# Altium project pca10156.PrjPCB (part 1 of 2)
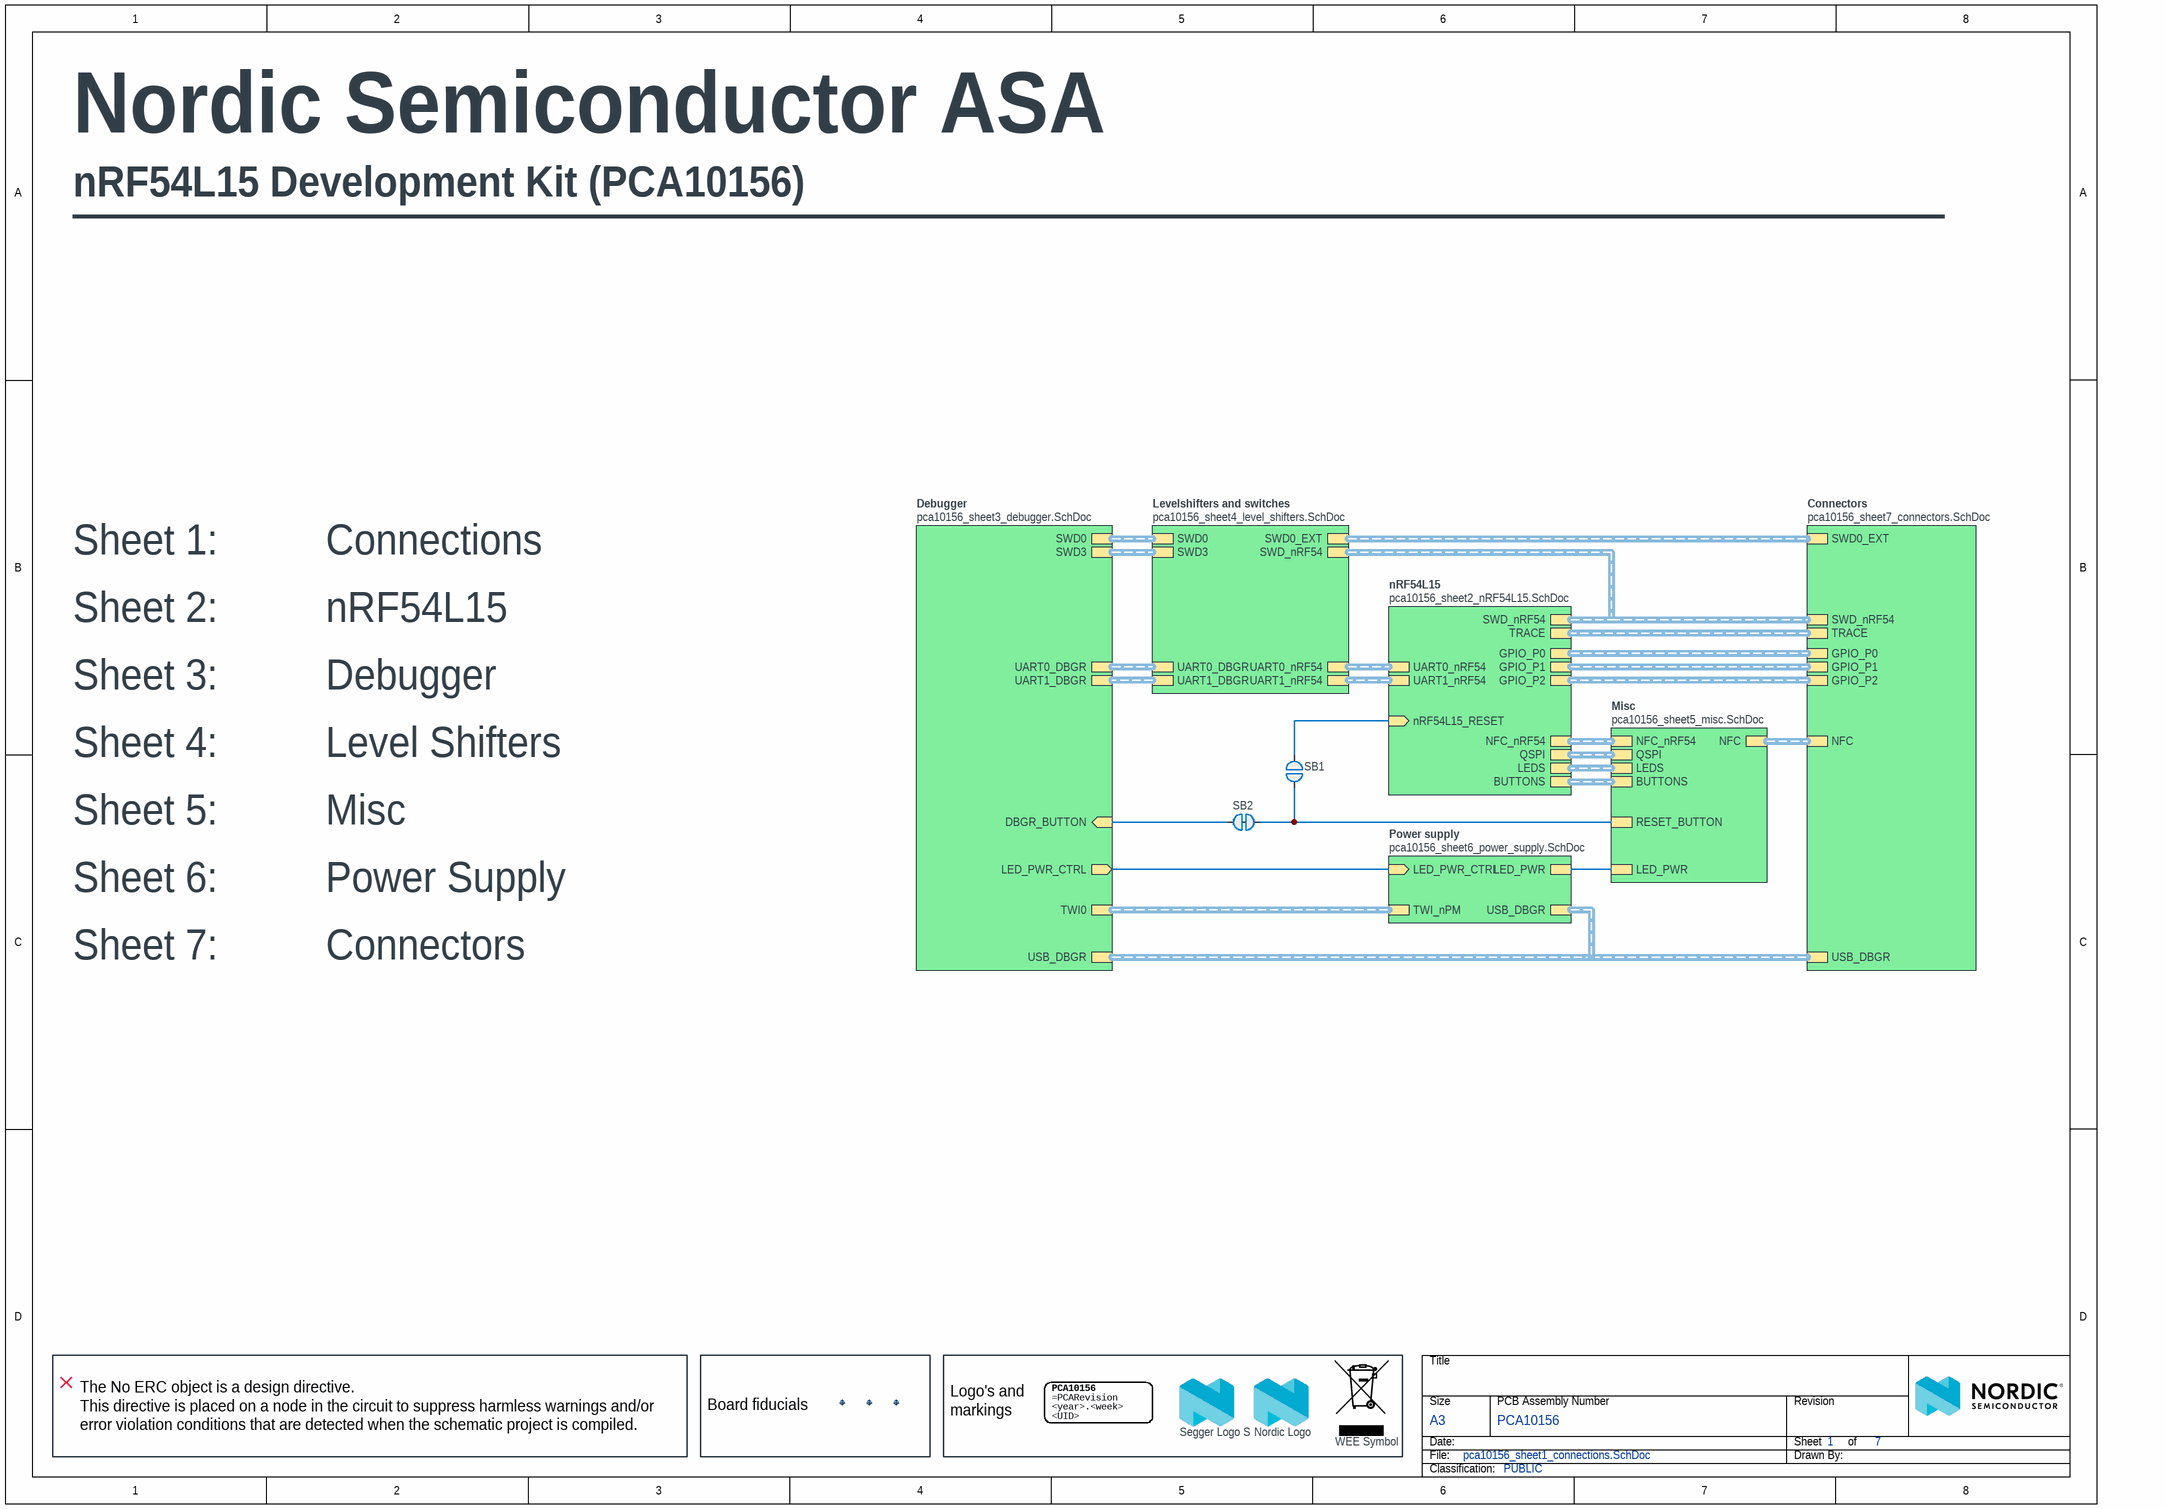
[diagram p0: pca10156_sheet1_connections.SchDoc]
BoardThickness: 1.6mm; BoardTitle: nRF54L15-DK; Classification: PUBLIC; Compliance: RoHS, REACH, Halogen-Free; Designer: STL1; Dielectric: FR-4; NrOfLayers: 4; Organization: Nordic Semiconductor; PCAName: PCA10156; PCARevision: 0.9.3; PCBNumber: 400708; PCBRevision: 0032STL1; PCBStackup: 4001; ProductName: nRF54L15-DK; SilkscreenColor: White; SoldermaskColor: Blue; SurfaceFinish: ENIG Gold
7 sheets, 207 parts. Net scope: hierarchical (ports join the sheet entries above them; power ports are global).
Board files: 400708.PcbDoc, 400708 _panel.PcbDoc
Sheets:
  pca10156_sheet1_connections.SchDoc
    nRF54L15 = pca10156_sheet2_nRF54L15.SchDoc
    Debugger = pca10156_sheet3_debugger.SchDoc
    Levelshifters and switches = pca10156_sheet4_level_shifters.SchDoc
    Misc = pca10156_sheet5_misc.SchDoc
    Power supply = pca10156_sheet6_power_supply.SchDoc
    Connectors = pca10156_sheet7_connectors.SchDoc

## Sheet pca10156_sheet1_connections.SchDoc: =BoardTitle+' - Connections'
size A3; Organization: Nordic Semiconductor; DocumentNumber: 1; Revision: 0.9.3; SheetNumber: 1; SheetTotal: 7; Author: STL1; CompanyName: Nordic Semiconductor; DrawnBy: STL1; DocumentSize: A4

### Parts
Fid1  Fiducial mark  [Fiducial]  (value not drawn)
Fid2  Fiducial mark  [Fiducial]  (value not drawn)
Fid3  Fiducial mark  [Fiducial]  (value not drawn)
LABEL1  12x12mm  [LabelSilk_12x12]  (value not drawn)
LOGO1  Nordic Logo  [NORDIC_LOGO_LYING]  (no BOM)
LOGO2  WEE Symbol  [WEE_3x4.5mm]  (no BOM)
LOGO3  Segger Logo S  [SEGGER_LOGO_S]  (no BOM)
SB1  Solderbridge  [Solderbridge]  (value not drawn)  (no BOM)
SB2  Solderbridge  [Solderbridge_Shorted]  (value not drawn)  (net tie, no BOM)

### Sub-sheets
Connectors = pca10156_sheet7_connectors.SchDoc: SWD_nRF54 (harness SWD), TRACE (harness TRACE), NFC (harness NFC), SWD0_EXT (harness SWD), GPIO_P0 (harness GPIO_P0), GPIO_P1 (harness GPIO_P1), GPIO_P2 (harness GPIO_P2), USB_DBGR (harness USB)
Debugger = pca10156_sheet3_debugger.SchDoc: DBGR_BUTTON (in), SWD0 (harness SWD), UART0_DBGR (harness UART_IMCU), USB_DBGR (harness USB), UART1_DBGR (harness UART_IMCU), TWI0 (harness TWI), SWD3 (harness SWD), LED_PWR_CTRL (out)
Levelshifters and switches = pca10156_sheet4_level_shifters.SchDoc: SWD0 (harness SWD), SWD0_EXT (harness SWD), UART0_nRF54 (harness UART), UART1_nRF54 (harness UART), SWD3 (harness SWD), SWD_nRF54 (harness SWD), UART0_DBGR (harness UART_IMCU), UART1_DBGR (harness UART_IMCU)
Misc = pca10156_sheet5_misc.SchDoc: NFC_nRF54 (harness NFC), NFC (harness NFC), BUTTONS (harness UI), LEDS (harness UI), RESET_BUTTON, QSPI (harness QSPI), LED_PWR
nRF54L15 = pca10156_sheet2_nRF54L15.SchDoc: BUTTONS (harness UI), LEDS (harness UI), TRACE (harness TRACE), NFC_nRF54 (harness NFC), GPIO_P0 (harness GPIO_P0), UART0_nRF54 (harness UART), GPIO_P1 (harness GPIO_P1), GPIO_P2 (harness GPIO_P2), UART1_nRF54 (harness UART), SWD_nRF54 (harness SWD), QSPI (harness QSPI), nRF54L15_RESET (in)
Power supply = pca10156_sheet6_power_supply.SchDoc: TWI_nPM (harness TWI), LED_PWR_CTRL (in), LED_PWR, USB_DBGR (harness USB)

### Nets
DBGR_BUTTON: SB2.2 ; sheet Debugger/DBGR_BUTTON
LED_PWR_CTRL: sheet Debugger/LED_PWR_CTRL, sheet Power supply/LED_PWR_CTRL
nRF54L15_RESET: SB1.1 ; sheet nRF54L15/nRF54L15_RESET
NetR1_2: sheet Misc/LED_PWR, sheet Power supply/LED_PWR
NetSB1_2: SB1.2 SB2.1 ; sheet Misc/RESET_BUTTON

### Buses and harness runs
harness sheet Connectors/GPIO_P0 = sheet nRF54L15/GPIO_P0
harness sheet Connectors/GPIO_P1 = sheet nRF54L15/GPIO_P1
harness sheet Connectors/GPIO_P2 = sheet nRF54L15/GPIO_P2
harness sheet Connectors/NFC = sheet Misc/NFC
harness sheet Connectors/SWD0_EXT = sheet Levelshifters and switches/SWD0_EXT
harness sheet Connectors/SWD_nRF54 = sheet Levelshifters and switches/SWD_nRF54 = sheet nRF54L15/SWD_nRF54
harness sheet Connectors/TRACE = sheet nRF54L15/TRACE
harness sheet Connectors/USB_DBGR = sheet Debugger/USB_DBGR = sheet Power supply/USB_DBGR
harness sheet Debugger/SWD0 = sheet Levelshifters and switches/SWD0
harness sheet Debugger/SWD3 = sheet Levelshifters and switches/SWD3
harness sheet Debugger/TWI0 = sheet Power supply/TWI_nPM
harness sheet Debugger/UART0_DBGR = sheet Levelshifters and switches/UART0_DBGR
harness sheet Debugger/UART1_DBGR = sheet Levelshifters and switches/UART1_DBGR
harness sheet Levelshifters and switches/UART0_nRF54 = sheet nRF54L15/UART0_nRF54
harness sheet Levelshifters and switches/UART1_nRF54 = sheet nRF54L15/UART1_nRF54
harness sheet Misc/BUTTONS = sheet nRF54L15/BUTTONS
harness sheet Misc/LEDS = sheet nRF54L15/LEDS
harness sheet Misc/NFC_nRF54 = sheet nRF54L15/NFC_nRF54
harness sheet Misc/QSPI = sheet nRF54L15/QSPI

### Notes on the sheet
- Nordic Semiconductor ASA
- nRF54L15 Development Kit (PCA10156)
- ________________________________________________________________
- Sheet 1:          Connections
- Sheet 2:          nRF54L15
- Sheet 3:          Debugger
- Sheet 4:          Level Shifters
- Sheet 5:          Misc
- Sheet 6:          Power Supply
- Sheet 7:          Connectors
- The No ERC object is a design directive.
  This directive is placed on a node in the circuit to suppress harmless warnings and/or error violation conditions that are detected when the schematic project is compiled.
- (near Fid1) Board fiducials
- (near LABEL1) Logo's and markings

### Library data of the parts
Fid1-Fid3 = Fid-Mark: Manufacturer: N.A.; Part number NEMS: 100500073; Value: N.A.; Pad Count: 1; Component Status: Active; System: Connector
LABEL1 = Label_12x12: PCA version label, stick-on, 12x12mm; Manufacturer: Ellco Etikett; Manufacturer Part Number: A33512‐01; Part number NEMS: 101200028; Component Status: Active; Pad Count: 0; Note: N.A.
LOGO1 = Nordic Logo lying: Manufacturer: N.A.; Part number NEMS: 101100001; Component Status: Active; Pad Count: 0
LOGO2 = WEEE Symbol 3x4.5mm: WEEE Directive symbol; Manufacturer: N.A.; Part number NEMS: 101100006; Component Status: Active; Pad Count: 0
LOGO3 = Segger Logo S: Segger logo, small size; Manufacturer: N.A.; Part number NEMS: 101100004; Component Status: Active; Pad Count: 0
SB1 = Solderbridge: Manufacturer: N.A.; Part number NEMS: 100500458; Pad Count: 2; Component Status: Active; System: Connector
SB2 = Solderbridge Shorted: Shorted Solderbridge; Manufacturer: N.A.; Part number NEMS: 100500459; Pad Count: 2; Component Status: Active; System: Connector

## Sheet pca10156_sheet2_nRF54L15.SchDoc: =BoardTitle+' - nRF54L15'
size A3; Organization: Nordic Semiconductor; DocumentNumber: 2; Revision: 0.9.3; SheetNumber: 2; SheetTotal: 7; Author: STL1; CompanyName: Nordic Semiconductor; DrawnBy: STL1; DocumentSize: A4
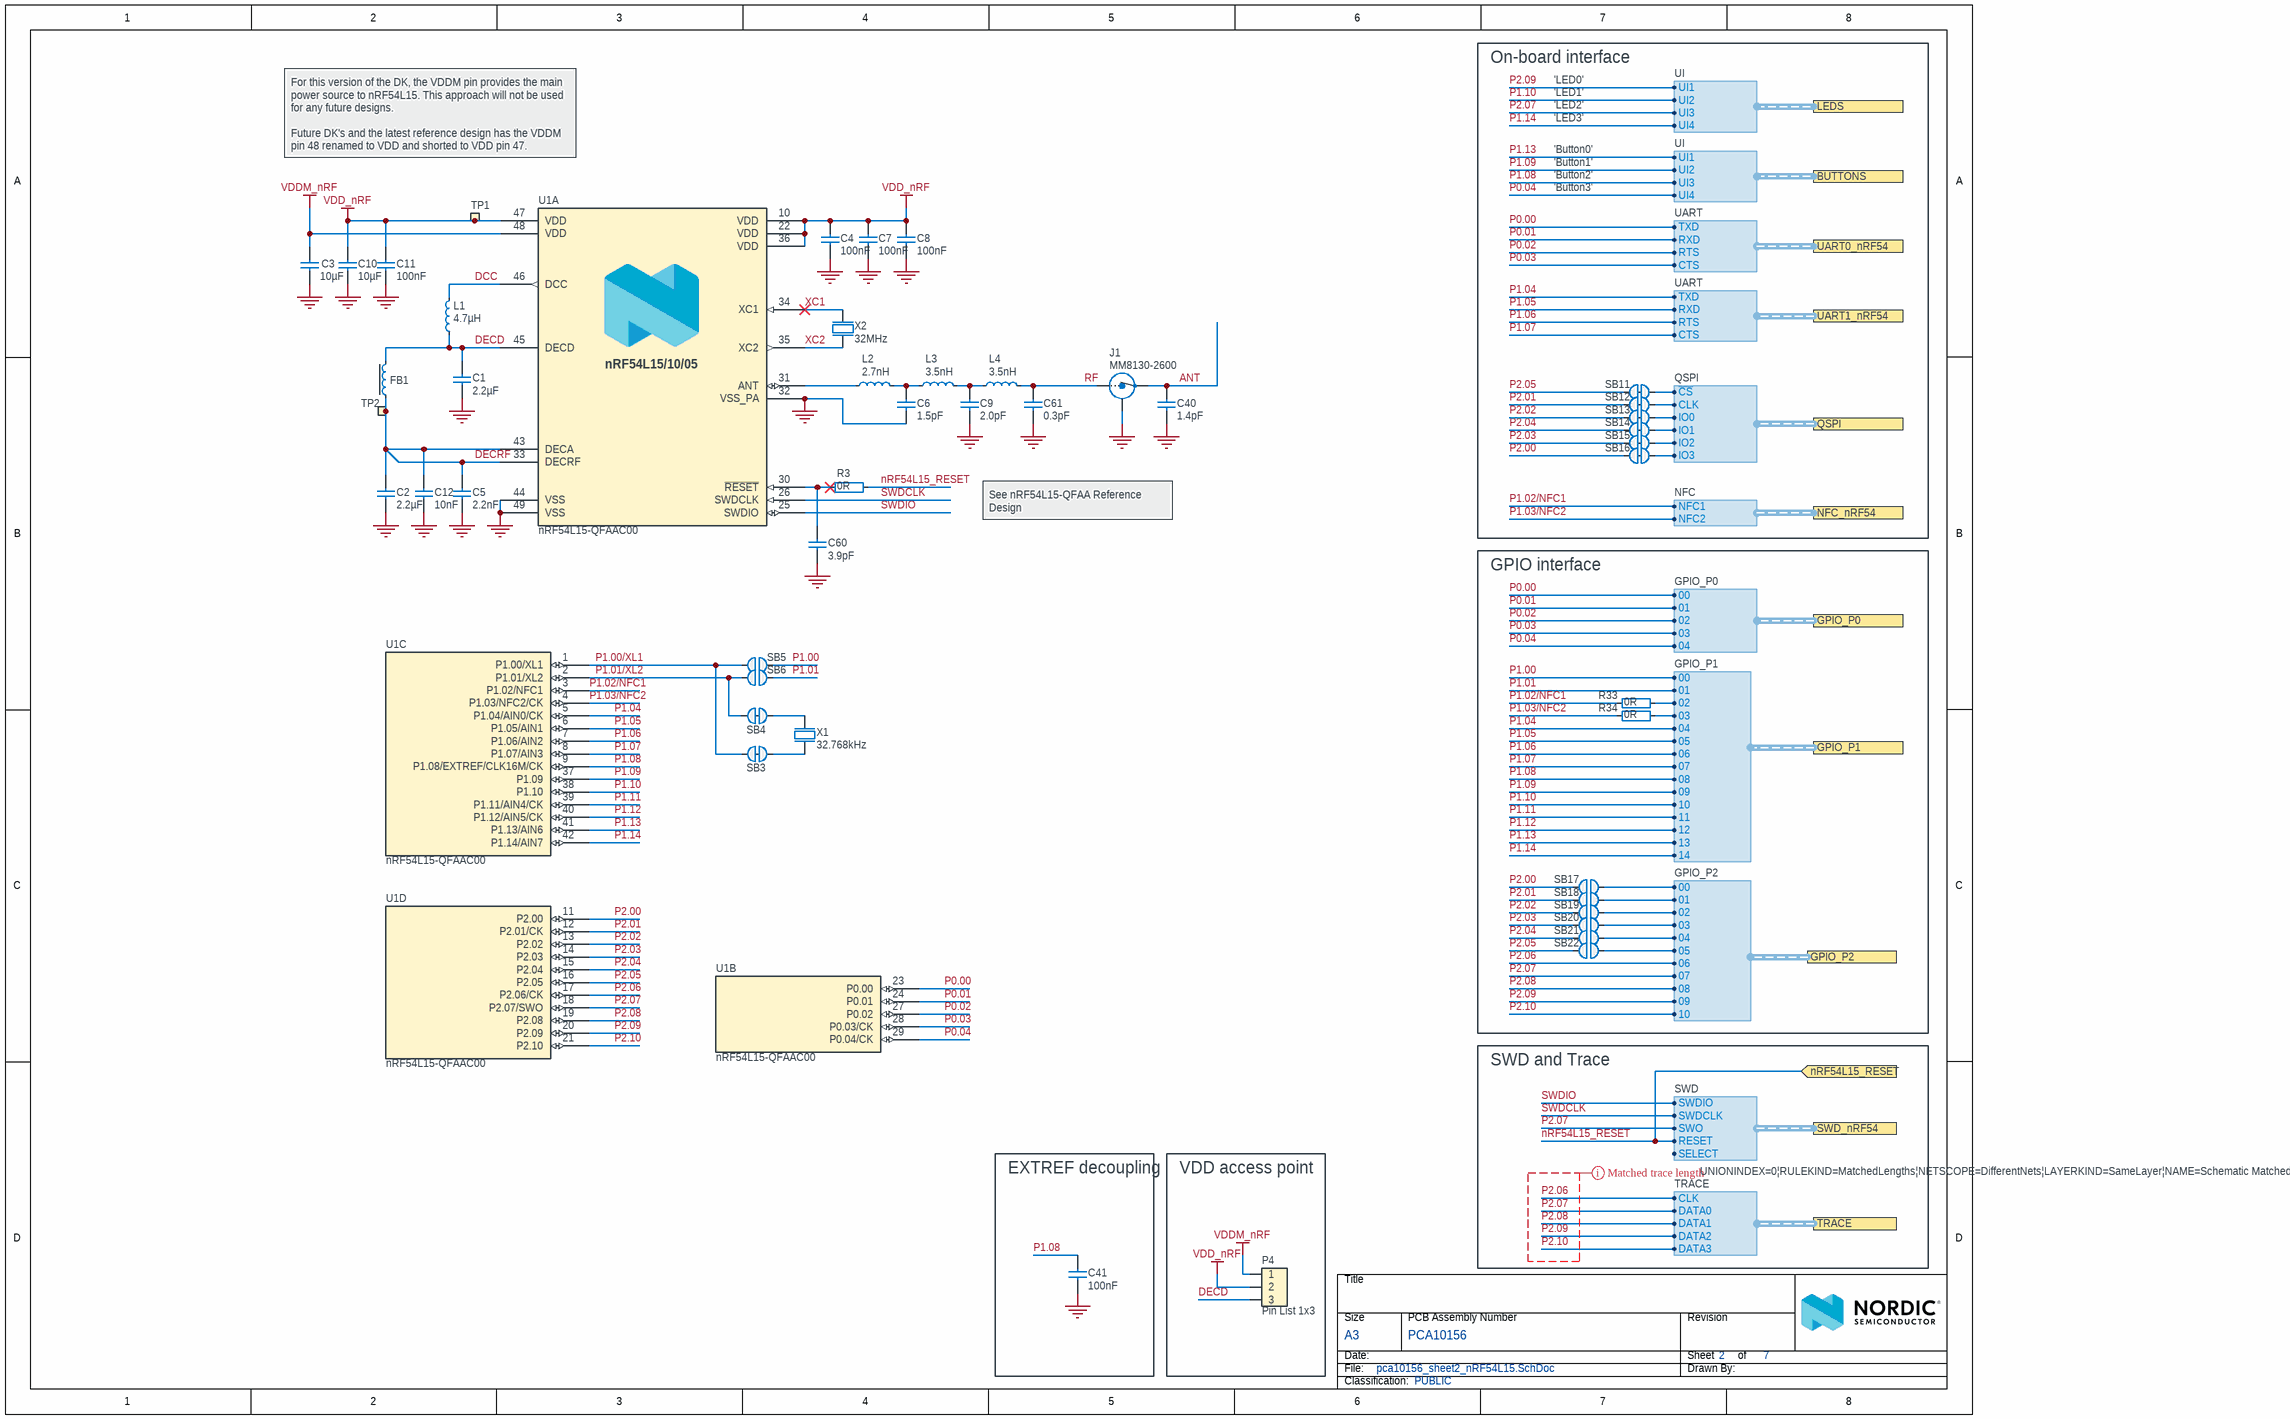
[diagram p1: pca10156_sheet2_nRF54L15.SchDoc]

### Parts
C1  2.2µF  [CAPC0603X03L_C]
C2  2.2µF  [CAPC0603X03L_C]
C3  10µF  [CAPC1005X04L]
C4  100nF  [CAPC0603X03L_C]
C5  2.2nF  [CAPC0603X03L_C]
C6  1.5pF  [CAPC0603X03L_C]
C7  100nF  [CAPC0603X03L_C]
C8  100nF  [CAPC0603X03L_C]
C9  2.0pF  [CAPC0603X03L_C]
C10  10µF  [CAPC1005X04L]
C11  100nF  [CAPC0603X03L_C]
C12  10nF  [CAPC0603X03L_C]
C40  1.4pF  [CAPC0603X03L_C]
C41  100nF  [CAPC1005X04L]
C60  3.9pF  [CAPC0603X03L_C]
C61  0.3pF  [CAPC0603X03L_C]
FB1  120R/0.2A  [INDC0603X03L_C]  (value not drawn)
J1  MM8130-2600  [COAXIAL-SWF]
L1  4.7µH  [INDC1608X06L]
L2  2.7nH  [INDC0603X03L_C]
L3  3.5nH  [INDC0603X03L_C]
L4  3.5nH  [INDC0603X03L_C]
P4  Pin List 1x3  [LIST_1x3]
R3  0R  [RESC0603X03L_C]
R33  0R  [RESC1005X04L]
R34  0R  [RESC1005X04L]
SB3  Solderbridge  [Solderbridge_SHORTED_0.4]  (value not drawn)  (net tie, no BOM)
SB4  Solderbridge  [Solderbridge_SHORTED_0.4]  (value not drawn)  (net tie, no BOM)
SB5  Solderbridge  [Solderbridge_0.4]  (value not drawn)  (no BOM)
SB6  Solderbridge  [Solderbridge_0.4]  (value not drawn)  (no BOM)
SB11  Solderbridge  [Solderbridge_SHORTED_0.4]  (value not drawn)  (net tie, no BOM)
SB12  Solderbridge  [Solderbridge_SHORTED_0.4]  (value not drawn)  (net tie, no BOM)
SB13  Solderbridge  [Solderbridge_SHORTED_0.4]  (value not drawn)  (net tie, no BOM)
SB14  Solderbridge  [Solderbridge_SHORTED_0.4]  (value not drawn)  (net tie, no BOM)
SB15  Solderbridge  [Solderbridge_SHORTED_0.4]  (value not drawn)  (net tie, no BOM)
SB16  Solderbridge  [Solderbridge_SHORTED_0.4]  (value not drawn)  (net tie, no BOM)
SB17  Solderbridge  [Solderbridge_0.4]  (value not drawn)  (no BOM)
SB18  Solderbridge  [Solderbridge_0.4]  (value not drawn)  (no BOM)
SB19  Solderbridge  [Solderbridge_0.4]  (value not drawn)  (no BOM)
SB20  Solderbridge  [Solderbridge_0.4]  (value not drawn)  (no BOM)
SB21  Solderbridge  [Solderbridge_0.4]  (value not drawn)  (no BOM)
SB22  Solderbridge  [Solderbridge_0.4]  (value not drawn)  (no BOM)
TP1  Ø1.5mm,SMD  [TP_SMD_D1.5mm]  (value not drawn)  (no BOM)
TP2  Ø1.5mm,SMD  [TP_SMD_D1.5mm]  (value not drawn)  (no BOM)
U1  nRF54L15-QFAAC00  [QFN40P600X600X90-48N]  (parts A,B,C,D of 4)
X1  32.768kHz  [XTAL_2012]
X2  32MHz  [BT-XTAL_2016]

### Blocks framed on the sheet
On-board interface: SB11-SB16
GPIO interface: R33 R34 SB17-SB22
EXTREF decoupling: C41
VDD access point: P4

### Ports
BUTTONS (harness UI), GPIO_P0 (harness GPIO_P0), GPIO_P1 (harness GPIO_P1), GPIO_P2 (harness GPIO_P2), LEDS (harness UI), NFC_nRF54 (harness NFC), nRF54L15_RESET (in), QSPI (harness QSPI), SWD_nRF54 (harness SWD), TRACE (harness TRACE), UART0_nRF54 (harness UART), UART1_nRF54 (harness UART)

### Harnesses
SWD: SWDIO, SWDCLK, SWO, RESET, SELECT
NFC: NFC2, NFC1
UART: RTS, CTS, RXD, TXD
GPIO_P1: 00, 01, 02, 03, 04, 05, 06, 07, 08, 09, 10, 11, 12, 13, 14
GPIO_P0: 02, 03, 04, 00, 01
GPIO_P2: 00, 01, 02, 03, 04, 05, 06, 07, 08, 09, 10
QSPI: ~{CS}, IO0, CLK, IO1, IO2, IO3
TRACE: CLK, DATA0, DATA1, DATA3, DATA2
UI: UI2, UI1, UI3, UI4

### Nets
GND: C1.1 C2.1 C3.1 C4.2 C5.1 C6.1 C7.2 C8.2 C9.1 C10.1 C11.2 C12.2 C40.1 C41.1 C60.2 C61.1 J1.2(Shield) U1.32(VSS_PA) U1.44(VSS) U1.49(VSS) X2.2(GND) X2.4(GND)
VDD_nRF: C4.1 C7.1 C8.1 C10.2 C11.1 P4.2 TP1.1 U1.10(VDD) U1.22(VDD) U1.36(VDD) U1.47(VDD)
VDDM_nRF: C3.2 P4.1 U1.48(VDD)
ANT: C40.2 J1.3(OUT)
DCC: L1.2 U1.46(DCC)
DECD: C1.2 FB1.1 L1.1 P4.3 U1.45(DECD)
DECRF: C2.2 C5.2 C12.1 FB1.2 TP2.1 U1.33(DECRF) U1.43(DECA)
nRF54L15_RESET: R3.2 ; port nRF54L15_RESET, port SWD_nRF54.RESET
P0.00: U1.23(P0.00) ; port UART0_nRF54.TXD, port GPIO_P0.00
P0.01: U1.24(P0.01) ; port UART0_nRF54.RXD, port GPIO_P0.01
P0.02: U1.27(P0.02) ; port UART0_nRF54.RTS, port GPIO_P0.02
P0.03: U1.28(P0.03/CK) ; port UART0_nRF54.CTS, port GPIO_P0.03
P0.04: U1.29(P0.04/CK) ; port GPIO_P0.04, port BUTTONS.UI4
P1.00: SB5.2 ; port GPIO_P1.00
P1.00/XL1: SB3.1 SB5.1 U1.1(P1.00/XL1)
P1.01: SB6.2 ; port GPIO_P1.01
P1.01/XL2: SB4.1 SB6.1 U1.2(P1.01/XL2)
P1.02/NFC1: R33.1 U1.3(P1.02/NFC1) ; port NFC_nRF54.NFC1
P1.03/NFC2: R34.1 U1.4(P1.03/NFC2/CK) ; port NFC_nRF54.NFC2
P1.04: U1.5(P1.04/AIN0/CK) ; port GPIO_P1.04, port UART1_nRF54.TXD
P1.05: U1.6(P1.05/AIN1) ; port GPIO_P1.05, port UART1_nRF54.RXD
P1.06: U1.7(P1.06/AIN2) ; port GPIO_P1.06, port UART1_nRF54.RTS
P1.07: U1.8(P1.07/AIN3) ; port GPIO_P1.07, port UART1_nRF54.CTS
P1.08: C41.2 U1.9(P1.08/EXTREF/CLK16M/CK) ; port GPIO_P1.08, port BUTTONS.UI3
P1.09: U1.37(P1.09) ; port GPIO_P1.09, port BUTTONS.UI2
P1.10: U1.38(P1.10) ; port GPIO_P1.10, port LEDS.UI2
P1.11: U1.39(P1.11/AIN4/CK) ; port GPIO_P1.11
P1.12: U1.40(P1.12/AIN5/CK) ; port GPIO_P1.12
P1.13: U1.41(P1.13/AIN6) ; port GPIO_P1.13, port BUTTONS.UI1
P1.14: U1.42(P1.14/AIN7) ; port GPIO_P1.14, port LEDS.UI4
P2.00: SB16.1 SB17.2 U1.11(P2.00)
P2.01: SB12.1 SB18.2 U1.12(P2.01/CK)
P2.02: SB13.1 SB19.2 U1.13(P2.02)
P2.03: SB15.1 SB20.2 U1.14(P2.03)
P2.04: SB14.1 SB21.2 U1.15(P2.04)
P2.05: SB11.1 SB22.2 U1.16(P2.05)
P2.06: U1.17(P2.06/CK) ; port GPIO_P2.06, port TRACE.CLK
P2.07: U1.18(P2.07/SWO) ; port SWD_nRF54.SWO, port GPIO_P2.07, port TRACE.DATA0, port LEDS.UI3
P2.08: U1.19(P2.08) ; port GPIO_P2.08, port TRACE.DATA1
P2.09: U1.20(P2.09) ; port GPIO_P2.09, port TRACE.DATA2, port LEDS.UI1
P2.10: U1.21(P2.10) ; port GPIO_P2.10, port TRACE.DATA3
RF: C61.2 J1.1(IN) L4.2
SWDCLK: U1.26(SWDCLK) ; port SWD_nRF54.SWDCLK
SWDIO: U1.25(SWDIO) ; port SWD_nRF54.SWDIO
XC1: U1.34(XC1) X2.1(inp)
XC2: U1.35(XC2) X2.3(out)
NetC6_2: C6.2 L2.2 L3.1
NetC9_2: C9.2 L3.2 L4.1
NetC60_1: C60.1 R3.1 U1.30(~{RESET})
NetL2_1: L2.1 U1.31(ANT)
NetP1_5: R33.2 ; port GPIO_P1.02
NetP1_6: R34.2 ; port GPIO_P1.03
NetP2_3: SB17.1 ; port GPIO_P2.00
NetP2_4: SB18.1 ; port GPIO_P2.01
NetP2_5: SB19.1 ; port GPIO_P2.02
NetP2_6: SB20.1 ; port GPIO_P2.03
NetP2_7: SB21.1 ; port GPIO_P2.04
NetP2_8: SB22.1 ; port GPIO_P2.05
NetSB3_2: SB3.2 X1.2(out)
NetSB4_2: SB4.2 X1.1(inp)
NetSB11_2: SB11.2 ; port QSPI.~{CS}
NetSB12_2: SB12.2 ; port QSPI.CLK
NetSB13_2: SB13.2 ; port QSPI.IO0
NetSB14_2: SB14.2 ; port QSPI.IO1
NetSB15_2: SB15.2 ; port QSPI.IO2
NetSB16_2: SB16.2 ; port QSPI.IO3

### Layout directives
net class TRACE; rule Matched Net Lengths [Delay Tolerance = 500ps]: P2.06, P2.07, P2.08, P2.09, P2.10

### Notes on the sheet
- 'LED1'
- 'LED0'
- For this version of the DK, the VDDM pin provides the main power source to nRF54L15. This approach will not be used for any future designs.
  Future DK's and the latest reference design has the VDDM pin 48 renamed to VDD and shorted to VDD pin 47.
- 'LED2'
- 'LED3'
- 'Button1'
- 'Button0'
- 'Button2'
- 'Button3'
- See nRF54L15-QFAA Reference Design
- SWD and Trace

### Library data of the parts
C1 C2 = C0201-2µ2-2.5V-X6T-GRM033D80E225ME47D: Capacitor, Ceramic, 2.2µF 2.5V X6T 0201,±20%; Manufacturer: Murata; Manufacturer Part Number: GRM033R61A225KE47; Part number NEMS: 100200527; Component Status: Active; Pad Count: 2; Note: 2.5V, 20%, X6T; Artikkelnr Noca: N.A.
C3 C10 = C0402-10µF-6.3V-X6S: Capacitor, X6S, ±20%, 6.3V; Manufacturer: N.A.; Part number NEMS: 100200478; Component Status: Active; Pad Count: 2
C4 C7 C8 C11 = C0201-100n: Capacitor, X5R, ±10%; Manufacturer: N.A.; Part number IPS: 00000001248, 00000002505; Part number Norautron: 262071862; Part number NEMS: 100200078; Pad Count: 2; Note: 16V; Component Status: Active
C5 = C0201-2n2: Capacitor, X7R, ±10%, 10V; Manufacturer: N.A.; Part number IPS: 00000001778; Part number Norautron: 26470002; Part number NEMS: 100200060; Pad Count: 2; Component Status: Active
C6 = C0201-1.5p-25V-NP0-GJM0335C1E1R5WB01: Capacitor, NP0, ±0.05pF, 25V, High Q; Manufacturer: Murata; Part number NEMS: 100200477; Component Status: Active; Pad Count: 2; Artikkelnr Noca: N.A.
C9 = C0201-2.0p-HQ-Murata: Capacitor, NP0, ±0.05pF, 25V; Manufacturer: Murata; Manufacturer Part Number: GJM0335C1E2R0WB01; Part number IPS: 00000001775; Part number NEMS: 100200419; Component Status: Active; Pad Count: 2; Artikkelnr Noca: N.A.
C12 = C0201-10n: Capacitor, X7R, ±10%; Manufacturer: N.A.; Part number IPS: 00000003480; Part number Norautron: 26621779; Part number NEMS: 100200067; Note: 10V; Pad Count: 2; Component Status: Active
C40 = C0201-1.4p-25V-GJM0335C1E1R4WB01D: Capacitor, C0G, ±0.05pF, 25V; Manufacturer: Murata; Part number NEMS: 100200553; Pad Count: 2; Artikkelnr Noca: N.A.; Component Status: Active
C41 = C0402-100n: Capacitor, X7R, ±10%; Manufacturer: N.A.; Part number IPS: 00000005296; Part number NEMS: 100200184; Component Status: Active; Pad Count: 2; Note: 16V; Artikkelnr Noca: 20039200; Assembly: Not Mounted
C60 = C0201-3.9p-HQ-Murata: Capacitor, NP0, ±0.05pF, 25V; Manufacturer: Murata; Manufacturer Part Number: GJM0333C1E3R9WB01; Part number NEMS: 100200424; Component Status: Active; Pad Count: 2; Artikkelnr Noca: N.A.
C61 = C0201-0.3p-50V-GRM0335C1HR30BA01: Capacitor, C0G, ±0.1pF, 50V; Manufacturer: Murata; Part number NEMS: 100200650; Component Status: Active; Pad Count: 2; Artikkelnr Noca: N.A.
FB1 = FB0201-120R@100M-200mA-BLM03AG121SN1D: Ferrite Bead, 120 Ohm @ 100MHz, 200mA, 500 mOhm Max; Manufacturer: Murata; Part number NEMS: 100300419; Component Status: Active; Pad Count: 2; Artikkelnr Noca: N.A.
J1 = MM8130-2600: Coaxial Connector with Switch; Manufacturer: Murata; Part number IPS: 00000009955; Part number Norautron: 26030338; Part number NEMS: 100500400; Component Status: Active; Pad Count: 3; Note: N.A.; Artikkelnr Noca: 55029011
L1 = L0603-4µ7-MLZ1608M4R7WT000: Inductor, 120mA, ±20%, 0.65R; Manufacturer: TDK Corporation; Part number NEMS: 100300440; Component Status: Active; Pad Count: 2; Note: Power Inductor ±20%; Artikkelnr Noca: N.A.
L2 = L0201-2n7-HQ-Murata: Inductor, 600mA, ±0.1ｎH, 120mOhm; Manufacturer: Murata; Manufacturer Part Number: LQP03HQ2N7B02; Part number IPS: 00000001753; Part number NEMS: 100300214; Component Status: Active; Pad Count: 2; Note: -55°C ~ 125°C; Artikkelnr Noca: N.A.
L3 L4 = L0201-3n5-HQ-Murata: Inductor, 500mA, ±0.1ｎH, 170mOhm; Manufacturer: Murata; Manufacturer Part Number: LQP03HQ3N5B02; Part number NEMS: 100300222; Component Status: Active; Pad Count: 2; Note: -55°C ~ 125°C; Artikkelnr Noca: N.A.
P4 = Pin List 1x3: Pin List 1x3, 2.54mm (100mil); Manufacturer: N.A.; Part number NEMS: 100500304; Component Status: Active; Pad Count: 3; Artikkelnr Noca: 56019041; Assembly: Not Mounted; System: Connector
R3 = R0201-0R: Resistor, ±5%, 0.05W; Manufacturer: N.A.; Part number IPS: 00000003245; Part number NEMS: 100100001; Component Status: Active; Pad Count: 2; Note: Chip Res 5%
R33 R34 = R0402-0R: Resistor, ±5%, 0.063W; Manufacturer: N.A.; Part number IPS: 00000007128; Part number NEMS: 100100109; Component Status: Active; Pad Count: 2; Note: Chip Res 5%; Artikkelnr Noca: 27049000; Assembly: Not Mounted
SB3 SB4 SB11-SB16 = Solderbridge Shorted 0.4mm: Shorted Solderbridge; Manufacturer: N.A.; Part number NEMS: 100500561; Component Status: Active; Pad Count: 2; System: Connector
SB5 SB6 SB17-SB22 = Solderbridge 0.4mm: Manufacturer: N.A.; Part number NEMS: 100500560; Component Status: Active; Pad Count: 2; System: Connector
TP1 TP2 = TP_SMD_Ø1.5MM: 1.5mm circular SMD testpad; Manufacturer: Nordic Semiconductor; Manufacturer Part Number: N.A.; Part number NEMS: 100500477; Pad Count: 1; Component Status: Active
U1 = nRF54L15-QFAAC00: Multi-protocol Bluetooth Low Energy, IEEE 802.15.4 and 2.4GHz proprietary Wireless MCU; Manufacturer: Nordic Semiconductor; Part number NEMS: 102000382; Component Status: Active; Pad Count: 49; Note: N.A.
X1 = XTAL_SMD2012_32.768kHz_9pF_TXC: XTAL SMD 2012, 32.768kHz, 9pF, ±20ppm; Manufacturer: TXC Corporation; Manufacturer Part Number: 9HT11-32.768KDZC-T; Part number NEMS: 101600107; Component Status: Active; Pad Count: 2; Note: XTAL SMD 32.768kHz; Artikkelnr Noca: N.A.
X2 = XTAL_SMD2016_32MHz_8pF_Golledge: XTAL SMD 2016, 32MHz, Cl=8pF, Tol: ±10ppm, Stab: ±15ppm; Manufacturer Part Number: MP06003; Part number IPS: 00000001431; Part number Norautron: N.A.; Part number NEMS: 101600041; Component Status: Active; Pad Count: 4; Note: XTAL SMD 32.000MHz; Artikkelnr Noca: 22010050

## Sheet pca10156_sheet3_debugger.SchDoc: =BoardTitle+' - Debugger'
size A3; Organization: Nordic Semiconductor; DocumentNumber: 3; Revision: 0.9.3; SheetNumber: 3; SheetTotal: 7; Author: STL1; CompanyName: Nordic Semiconductor; DrawnBy: STL1; DocumentSize: A4
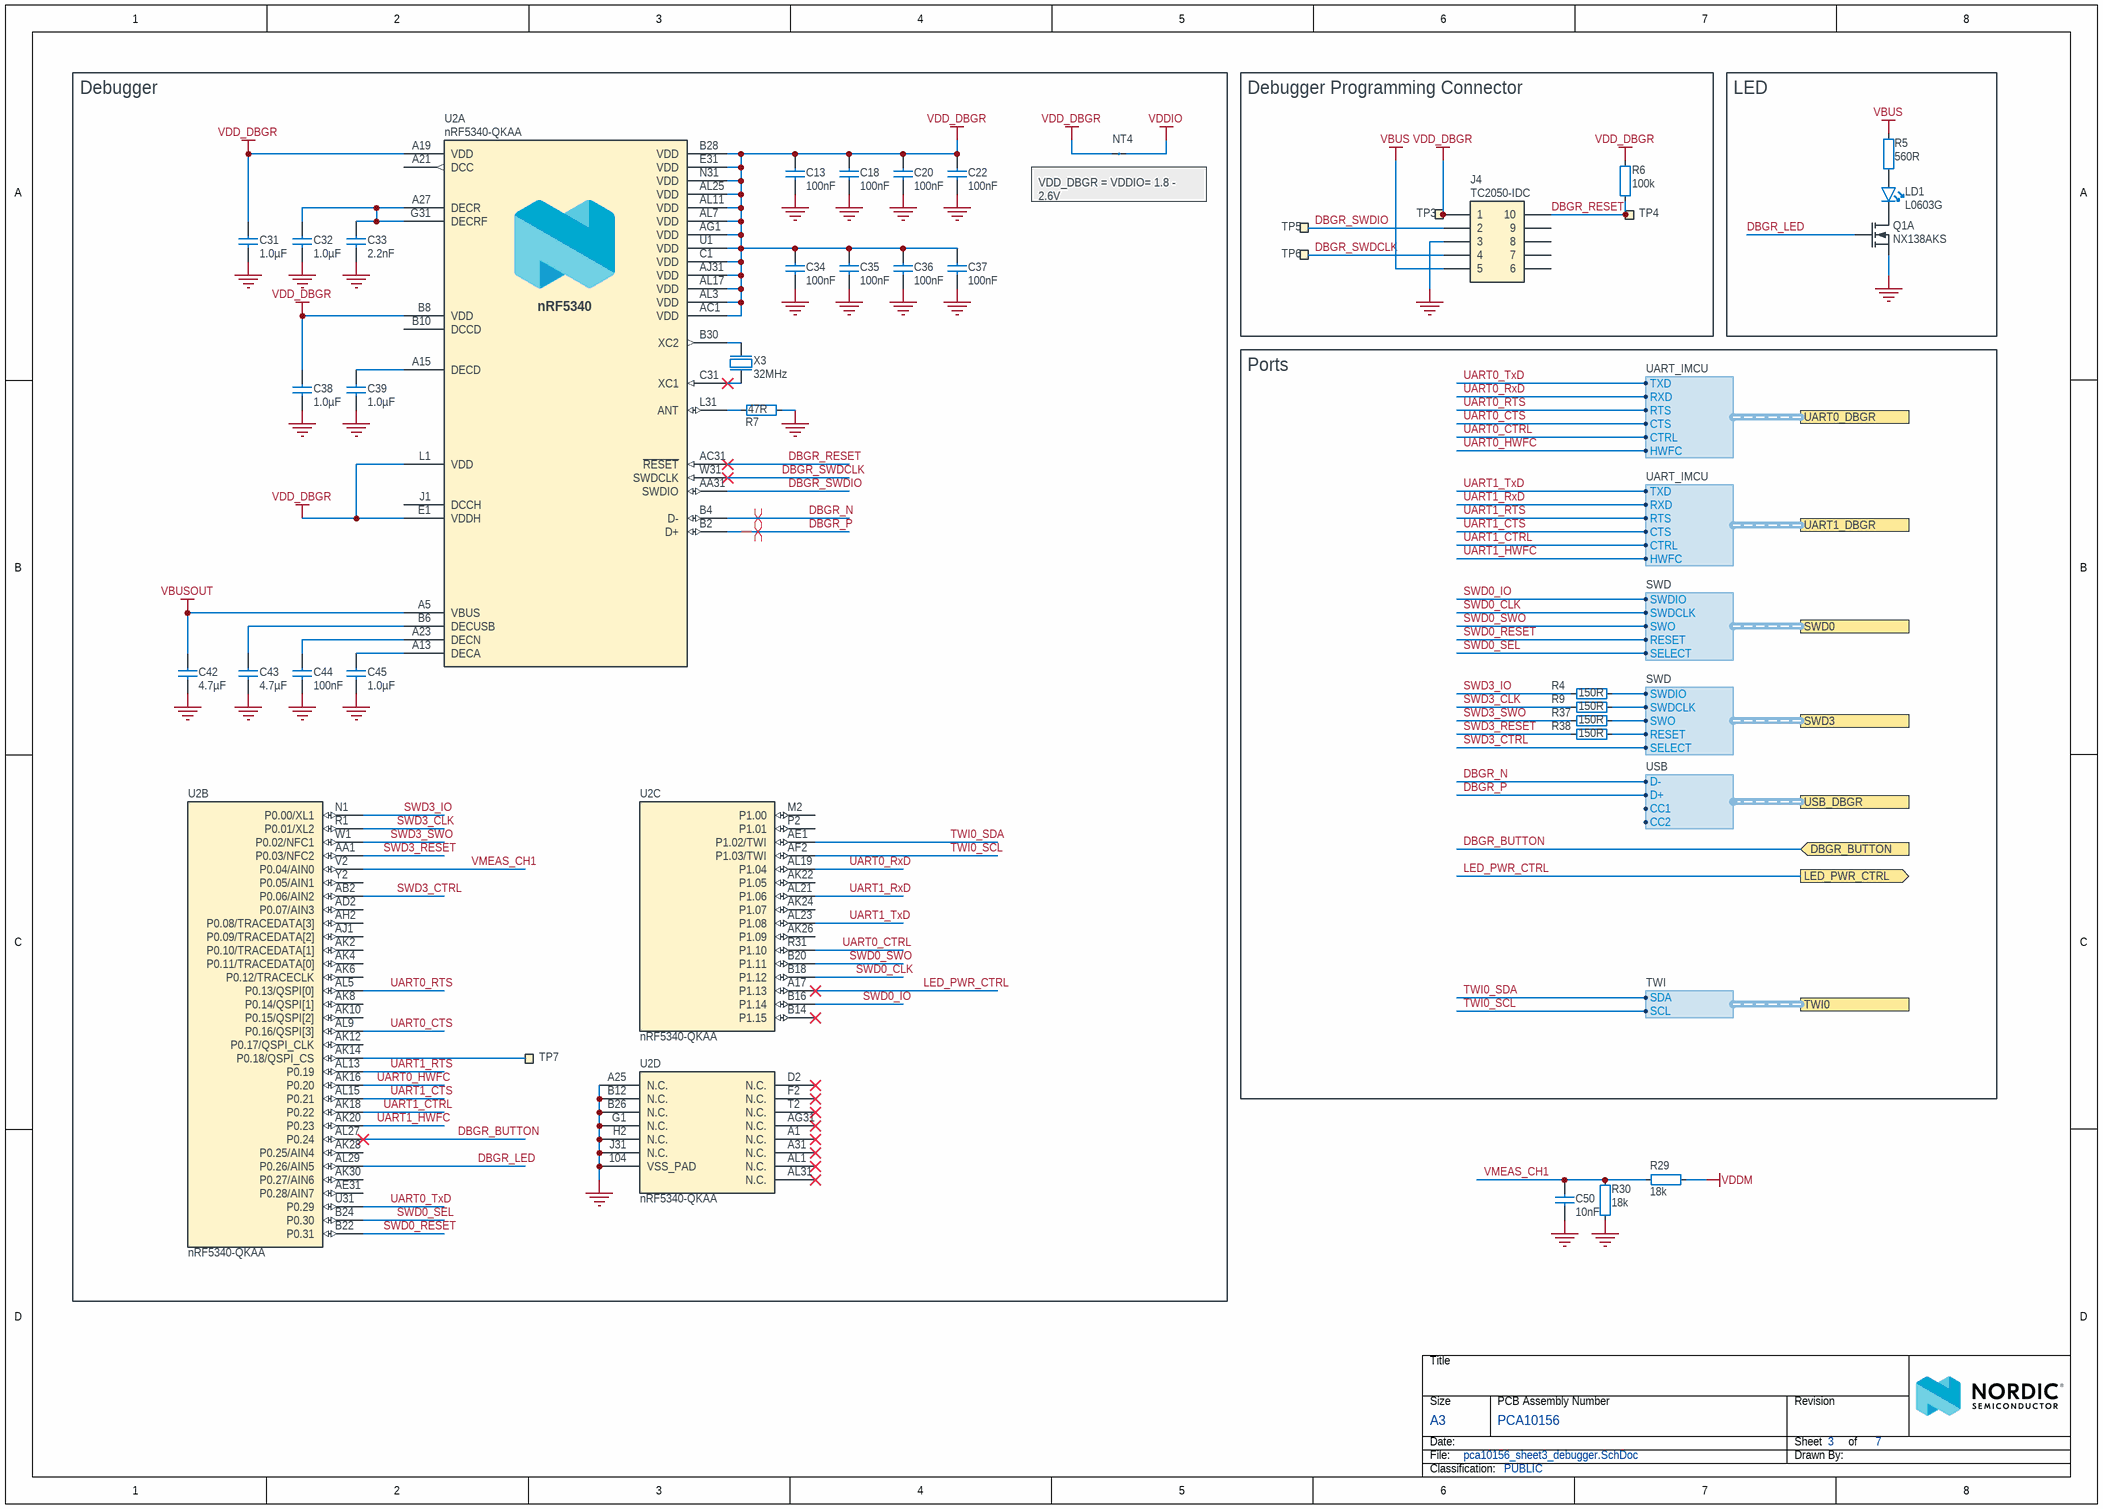
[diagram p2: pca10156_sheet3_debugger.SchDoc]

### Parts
C13  100nF  [CAPC0603X03L_C]
C18  100nF  [CAPC0603X03L_C]
C20  100nF  [CAPC0603X03L_C]
C22  100nF  [CAPC0603X03L_C]
C31  1.0µF  [CAPC1005X04L]
C32  1.0µF  [CAPC1005X04L]
C33  2.2nF  [CAPC0603X03L_C]
C34  100nF  [CAPC0603X03L_C]
C35  100nF  [CAPC0603X03L_C]
C36  100nF  [CAPC0603X03L_C]
C37  100nF  [CAPC0603X03L_C]
C38  1.0µF  [CAPC1005X04L]
C39  1.0µF  [CAPC1005X04L]
C42  4.7µF  [CAPC1608X06L]
C43  4.7µF  [CAPC1608X06L]
C44  100nF  [CAPC0603X03L_C]
C45  1.0µF  [CAPC1005X04L]
C50  10nF  [CAPC0603X03L_C]
J4  TC2050-IDC  [TC2050-IDC-NLFP]  (no BOM)
LD1  L0603G  [LED_0603_G]
NT4  N.A.  [2 pin starpoint 20mil]  (value not drawn)  (net tie, no BOM)
Q1  NX138AKS  [TSSOP6]  (part A of 2)
R4  150R  [RESC0603X03L_C]
R5  560R  [RESC0603X03L_C]
R6  100k  [RESC0603X03L_C]
R7  47R  [RESC0603X03L_C]
R9  150R  [RESC0603X03L_C]
R29  18k  [RESC0603X03L_C]
R30  18k  [RESC0603X03L_C]
R37  150R  [RESC0603X03L_C]
R38  150R  [RESC0603X03L_C]
TP3  Ø1.5mm,SMD  [TP_SMD_D1.5mm]  (value not drawn)  (no BOM)
TP4  Ø1.5mm,SMD  [TP_SMD_D1.5mm]  (value not drawn)  (no BOM)
TP5  Ø1.5mm,SMD  [TP_SMD_D1.5mm]  (value not drawn)  (no BOM)
TP6  Ø1.5mm,SMD  [TP_SMD_D1.5mm]  (value not drawn)  (no BOM)
TP7  Ø1.5mm,SMD  [TP_SMD_D1.5mm]  (value not drawn)  (no BOM)
U2  nRF5340-QKAA  [AQFN40P700X700X85_HS-99N]  (parts A,B,C,D of 4)
X3  32MHz  [BT-XTAL_2016]

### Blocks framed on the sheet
Debugger: C13 C18 C20 C22 C31-C39 C42-C45 NT4 R7 TP7 U2 X3
Debugger Programming Connector: J4 R6 TP3-TP6
LED: LD1 Q1 R5
Ports: R4 R9 R37 R38

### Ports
DBGR_BUTTON (in), LED_PWR_CTRL (out), SWD0 (harness SWD), SWD3 (harness SWD), TWI0 (harness TWI), UART0_DBGR (harness UART_IMCU), UART1_DBGR (harness UART_IMCU), USB_DBGR (harness USB)

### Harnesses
SWD: SWDIO, SWDCLK, SWO, RESET, SELECT
UART_IMCU: RTS, CTS, RXD, TXD, HWFC, CTRL
TWI: SCL, SDA
USB: D+, D-, CC1, CC2

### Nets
GND: C13.2 C18.2 C20.2 C22.2 C31.2 C32.1 C33.2 C34.2 C35.2 C36.2 C37.2 C38.1 C39.1 C42.2 C43.2 C44.2 C45.1 C50.2 J4.3 Q1.1(S1) R7.2 R30.1 U2.104(VSS_PAD) U2.A25(N.C.) U2.B12(N.C.) U2.B26(N.C.) U2.G1(N.C.) U2.H2(N.C.) U2.J31(N.C.) X3.2(GND) X3.4(GND)
VBUS: J4.5 R5.2
VBUSOUT: C42.1 U2.A5(VBUS)
VDD_DBGR: C13.1 C18.1 C20.1 C22.1 C31.1 C34.1 C35.1 C36.1 C37.1 C38.2 J4.1 NT4.1 R6.2 TP3.1 U2.A19(VDD) U2.AC1(VDD) U2.AG1(VDD) U2.AJ31(VDD) U2.AL3(VDD) U2.AL7(VDD) U2.AL11(VDD) U2.AL17(VDD) U2.AL25(VDD) U2.B8(VDD) U2.B28(VDD) U2.C1(VDD) U2.E1(VDDH) U2.E31(VDD) U2.L1(VDD) U2.N31(VDD) U2.U1(VDD)
VDDIO: NT4.2
VDDM: R29.2
DBGR_BUTTON: U2.AL27(P0.24) ; port DBGR_BUTTON
DBGR_LED: Q1.2(G1) U2.AL29(P0.26/AIN5)
DBGR_N: U2.B4(D-) ; port USB_DBGR.D-
DBGR_P: U2.B2(D+) ; port USB_DBGR.D+
DBGR_RESET: J4.10 R6.1 TP4.1 U2.AC31(~{RESET})
DBGR_SWDCLK: J4.4 TP6.1 U2.W31(SWDCLK)
DBGR_SWDIO: J4.2 TP5.1 U2.AA31(SWDIO)
LED_PWR_CTRL: U2.A17(P1.13) ; port LED_PWR_CTRL
SWD0_CLK: U2.B18(P1.12) ; port SWD0.SWDCLK
SWD0_IO: U2.B16(P1.14) ; port SWD0.SWDIO
SWD0_RESET: U2.B22(P0.31) ; port SWD0.RESET
SWD0_SEL: U2.B24(P0.30) ; port SWD0.SELECT
SWD0_SWO: U2.B20(P1.11) ; port SWD0.SWO
SWD3_CLK: R9.1 U2.R1(P0.01/XL2)
SWD3_CTRL: U2.AB2(P0.06/AIN2) ; port SWD3.SELECT
SWD3_IO: R4.1 U2.N1(P0.00/XL1)
SWD3_RESET: R38.1 U2.AA1(P0.03/NFC2)
SWD3_SWO: R37.1 U2.W1(P0.02/NFC1)
TWI0_SCL: U2.AF2(P1.03/TWI) ; port TWI0.SCL
TWI0_SDA: U2.AE1(P1.02/TWI) ; port TWI0.SDA
UART0_CTRL: U2.R31(P1.10) ; port UART0_DBGR.CTRL
UART0_CTS: U2.AL9(P0.16/QSPI[3]) ; port UART0_DBGR.CTS
UART0_HWFC: U2.AK16(P0.20) ; port UART0_DBGR.HWFC
UART0_RTS: U2.AL5(P0.13/QSPI[0]) ; port UART0_DBGR.RTS
UART0_RxD: U2.AL19(P1.04) ; port UART0_DBGR.RXD
UART0_TxD: U2.U31(P0.29) ; port UART0_DBGR.TXD
UART1_CTRL: U2.AK18(P0.22) ; port UART1_DBGR.CTRL
UART1_CTS: U2.AL15(P0.21) ; port UART1_DBGR.CTS
UART1_HWFC: U2.AK20(P0.23) ; port UART1_DBGR.HWFC
UART1_RTS: U2.AL13(P0.19) ; port UART1_DBGR.RTS
UART1_RxD: U2.AL21(P1.06) ; port UART1_DBGR.RXD
UART1_TxD: U2.AL23(P1.08) ; port UART1_DBGR.TXD
VMEAS_CH1: C50.1 R29.1 R30.2 U2.V2(P0.04/AIN0)
NetC32_2: C32.2 C33.1 U2.A27(DECR) U2.G31(DECRF)
NetC39_2: C39.2 U2.A15(DECD)
NetC43_1: C43.1 U2.B6(DECUSB)
NetC44_1: C44.1 U2.A23(DECN)
NetC45_2: C45.2 U2.A13(DECA)
NetLD1_1: LD1.1(C) Q1.6(D1)
NetLD1_2: LD1.2(A) R5.1
NetR4_2: R4.2 ; port SWD3.SWDIO
NetR7_1: R7.1 U2.L31(ANT)
NetR9_2: R9.2 ; port SWD3.SWDCLK
NetR37_2: R37.2 ; port SWD3.SWO
NetR38_2: R38.2 ; port SWD3.RESET
NetTP7_1: TP7.1 U2.AK14(P0.18/QSPI_CS)
NetU2_B30: U2.B30(XC2) X3.3(out)
NetU2_C31: U2.C31(XC1) X3.1(inp)

Not connected (* = marked no-connect by the designer): J4 6 7 8 9; U2 A1(N.C.)* A21(DCC) A31(N.C.)* AD2(P0.07/AIN3) AE31(P0.28/AIN7) AG31(N.C.)* AH2(P0.08/TRACEDATA[3]) AJ1(P0.09/TRACEDATA[2]) AK2(P0.10/TRACEDATA[1]) AK4(P0.11/TRACEDATA[0]) AK6(P0.12/TRACECLK) AK8(P0.14/QSPI[1]) AK10(P0.15/QSPI[2]) AK12(P0.17/QSPI_CLK) AK22(P1.05) AK24(P1.07) AK26(P1.09) AK28(P0.25/AIN4) AK30(P0.27/AIN6) AL1(N.C.)* AL31(N.C.)* B10(DCCD) B14(P1.15)* D2(N.C.)* F2(N.C.)* J1(DCCH) M2(P1.00) P2(P1.01) T2(N.C.)* Y2(P0.05/AIN1)

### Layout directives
differential pair; differential pair class IMCU; net class IMCU_USB: DBGR_N, DBGR_P

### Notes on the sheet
- (near NT4) VDD_DBGR = VDDIO= 1.8 - 2.6V

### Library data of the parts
C13 C18 C20 C22 C34-C37 C44 = C0201-100n: as C4 on sheet pca10156_sheet2_nRF54L15
C31 C32 C38 C39 C45 = C0402-1µ0-6.3V-X5R-10%: Capacitor, X5R, ±10%, 6.3V; Manufacturer: N.A.; Part number Norautron: 26207137; Part number NEMS: 100200498; Pad Count: 2; Component Status: Active
C33 = C0201-2n2: as C5 on sheet pca10156_sheet2_nRF54L15
C42 C43 = C0603-4µ7-10V-X7S: Capacitor, X7S, ±10%, 10V; Manufacturer: N.A.; Part number IPS: 00000001779; Part number NEMS: 100200351; Pad Count: 2; Artikkelnr Noca: 20030013; Component Status: Active
C50 = C0201-10n: Capacitor, X7R, ±10%; Manufacturer: N.A.; Part number IPS: 00000003480; Part number Norautron: 26621779; Part number NEMS: 100200067; Note: 10V; Assembly: Not Mounted; Pad Count: 2; Component Status: Active
J4 = TC2050-IDC-NLFP: CBL PLUG-OF-NAILS 10-PIN; Manufacturer: Tag-Connect LLC; Part number NEMS: 100500463; Artikkelnr Noca: N.A.; Pad Count: 10; Component Status: Active; System: Connector
LD1 = VS 25C7M5: LED, Green, 0603, 573nm, Vf=2.0V, 24mcd, - 40 to +85°C; Manufacturer: Victory Electronics; Part number IPS: 00000001274, 00000009961; Part number Norautron: 26313411; Part number NEMS: 101400097; Pad Count: 2; Note: N.A.; Artikkelnr Noca: 13019193; Component Status: Active
NT4 = 2 pin starpoint 20mil: Starpoint; Part number NEMS: 100500717; Component Status: Active; Pad Count: 2; System: Connector
Q1 = NX138AKS: MOSFET 2N-CH 60V 0.17A TSSOP6 (SOT363); Manufacturer: Nexperia; Manufacturer Part Number: NX138AKSX; Part number NEMS: 101300207; Component Status: Active; Pad Count: 6; Note: N.A.
R4 R9 R37 R38 = R0201-150: Resistor, ±1%, 0.05W; Manufacturer: N.A.; Part number IPS: 00000001420; Part number NEMS: 100100029; Note: Chip Res 1%; Pad Count: 2; Component Status: Active
R5 = R0201-560: Resistor, ±1%, 0.05W; Manufacturer: N.A.; Part number NEMS: 100100038; Note: Chip Res 1%; Pad Count: 2; Component Status: Active
R6 = R0201-100k: Resistor, ±1%, 0.05W; Manufacturer: N.A.; Part number IPS: 00000001419; Part number Norautron: 26108487; Part number NEMS: 100100080; Note: Chip Res 1%; Pad Count: 2; Component Status: Active
R7 = R0201-47R: Resistor, ±1%, 0.05W; Manufacturer: N.A.; Part number IPS: 00000004794; Part number Norautron: 26108300; Part number NEMS: 100100022; Component Status: Active; Pad Count: 2; Note: Chip Res 1%
R29 R30 = R0201-18k: Resistor, ±1%, 0.05W; Manufacturer: N.A.; Part number IPS: 00000001707; Part number NEMS: 100100069; Component Status: Active; Pad Count: 2; Note: Chip Res 1%; Assembly: Not Mounted
TP3-TP7 = TP_SMD_Ø1.5MM: as TP1 on sheet pca10156_sheet2_nRF54L15
U2 = nRF5340-QKAAD0: Multi-protocol Bluetooth Low Energy, IEEE 802.15.4, ANT and 2.4GHz proprietary system-on-chip; Manufacturer: Nordic Semiconductor; Part number Norautron: NOD26470035; Part number NEMS: 102000216; Pad Count: 98; Note: N.A.; Component Status: Active
X3 = XTAL_SMD2016_32MHz_8pF_Golledge: as X2 on sheet pca10156_sheet2_nRF54L15

## Sheet pca10156_sheet4_level_shifters.SchDoc: =BoardTitle+' - Level Shifters'
size A3; Organization: Nordic Semiconductor; DocumentNumber: 4; Revision: 0.9.3; SheetNumber: 4; SheetTotal: 7; Author: STL1; CompanyName: Nordic Semiconductor; DrawnBy: STL1; DocumentSize: A4
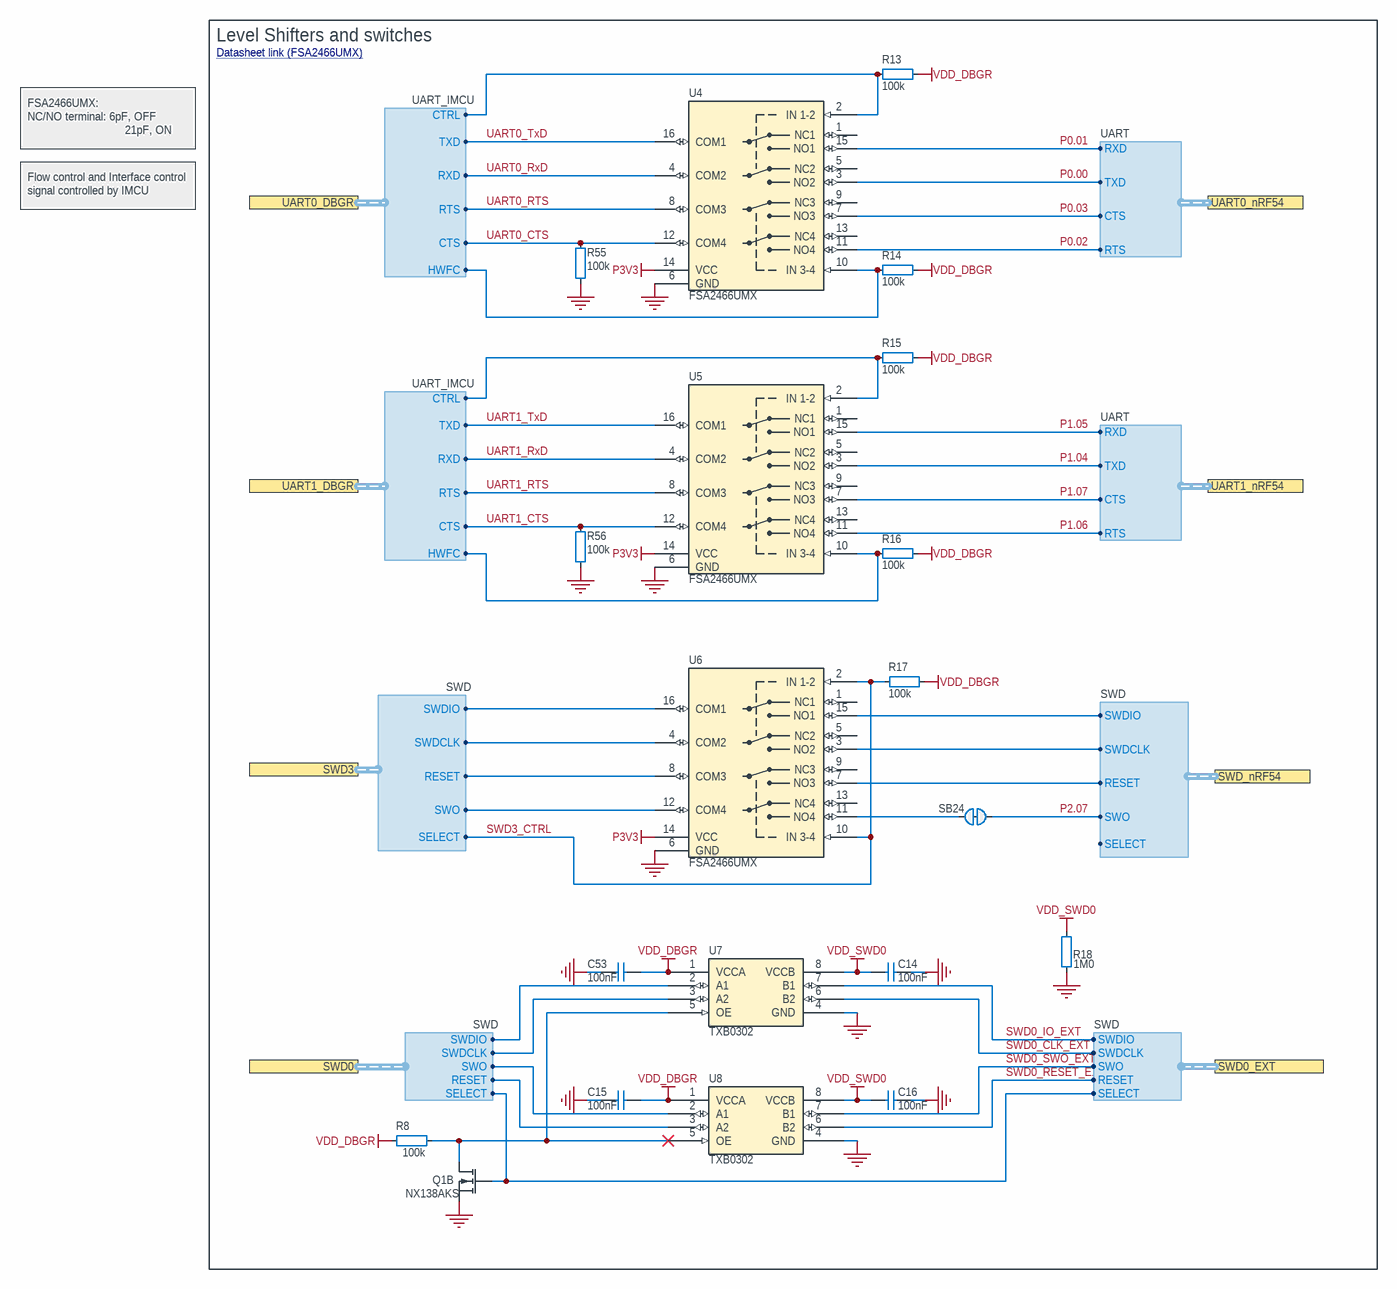
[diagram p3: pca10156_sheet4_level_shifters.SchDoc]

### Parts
C14  100nF  [CAPC0603X03L_C]
C15  100nF  [CAPC0603X03L_C]
C16  100nF  [CAPC0603X03L_C]
C53  100nF  [CAPC0603X03L_C]
Q1  NX138AKS  [TSSOP6]  (part B of 2)
R8  100k  [RESC0603X03L_C]
R13  100k  [RESC0603X03L_C]
R14  100k  [RESC0603X03L_C]
R15  100k  [RESC0603X03L_C]
R16  100k  [RESC0603X03L_C]
R17  100k  [RESC0603X03L_C]
R18  1M0  [RESC0603X03L_C]
R55  100k  [RESC0603X03L_C]
R56  100k  [RESC0603X03L_C]
SB24  Solderbridge  [Solderbridge_SHORTED_0.4]  (value not drawn)  (net tie, no BOM)
U4  FSA2466UMX  [XQFN40P180X260X50-16N]
U5  FSA2466UMX  [XQFN40P180X260X50-16N]
U6  FSA2466UMX  [XQFN40P180X260X50-16N]
U7  TXB0302  [XFDFN40P180X120X40-8M]
U8  TXB0302  [XFDFN40P180X120X40-8M]

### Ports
SWD0 (harness SWD), SWD0_EXT (harness SWD), SWD3 (harness SWD), SWD_nRF54 (harness SWD), UART0_DBGR (harness UART_IMCU), UART0_nRF54 (harness UART), UART1_DBGR (harness UART_IMCU), UART1_nRF54 (harness UART)

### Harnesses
SWD: SWDIO, SWDCLK, SWO, RESET, SELECT
UART_IMCU: RTS, CTS, RXD, TXD, HWFC, CTRL
UART: RTS, CTS, RXD, TXD

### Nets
GND: C14.2 C15.1 C16.2 C53.1 Q1.4(S2) R18.1 R55.2 R56.2 U4.6(GND) U5.6(GND) U6.6(GND) U7.4(GND) U8.4(GND)
P3V3: U4.14(VCC) U5.14(VCC) U6.14(VCC)
VDD_DBGR: C15.2 C53.2 R8.2 R13.1 R14.1 R15.1 R16.1 R17.1 U7.1(VCCA) U8.1(VCCA)
VDD_SWD0: C14.1 C16.1 R18.2 U7.8(VCCB) U8.8(VCCB)
nRF54L15_RESET: U6.7(NO3) ; port SWD_nRF54.RESET
P0.00: U4.3(NO2) ; port UART0_nRF54.TXD
P0.01: U4.15(NO1) ; port UART0_nRF54.RXD
P0.02: U4.11(NO4) ; port UART0_nRF54.RTS
P0.03: U4.7(NO3) ; port UART0_nRF54.CTS
P1.04: U5.3(NO2) ; port UART1_nRF54.TXD
P1.05: U5.15(NO1) ; port UART1_nRF54.RXD
P1.06: U5.11(NO4) ; port UART1_nRF54.RTS
P1.07: U5.7(NO3) ; port UART1_nRF54.CTS
P2.07: SB24.2 ; port SWD_nRF54.SWO
SWD0_CLK: U7.3(A2) ; port SWD0.SWDCLK
SWD0_CLK_EXT: U7.6(B2) ; port SWD0_EXT.SWDCLK
SWD0_IO: U7.2(A1) ; port SWD0.SWDIO
SWD0_IO_EXT: U7.7(B1) ; port SWD0_EXT.SWDIO
SWD0_RESET: U8.3(A2) ; port SWD0.RESET
SWD0_RESET_EXT: U8.6(B2) ; port SWD0_EXT.RESET
SWD0_SEL: Q1.5(G2) ; port SWD0.SELECT, port SWD0_EXT.SELECT
SWD0_SWO: U8.2(A1) ; port SWD0.SWO
SWD0_SWO_EXT: U8.7(B1) ; port SWD0_EXT.SWO
SWD3_CTRL: R17.2 U6.2(IN_1-2) U6.10(IN_3-4) ; port SWD3.SELECT
SWDCLK: U6.3(NO2) ; port SWD_nRF54.SWDCLK
SWDIO: U6.15(NO1) ; port SWD_nRF54.SWDIO
UART0_CTRL: R13.2 U4.2(IN_1-2) ; port UART0_DBGR.CTRL
UART0_CTS: R55.1 U4.12(COM4) ; port UART0_DBGR.CTS
UART0_HWFC: R14.2 U4.10(IN_3-4) ; port UART0_DBGR.HWFC
UART0_RTS: U4.8(COM3) ; port UART0_DBGR.RTS
UART0_RxD: U4.4(COM2) ; port UART0_DBGR.RXD
UART0_TxD: U4.16(COM1) ; port UART0_DBGR.TXD
UART1_CTRL: R15.2 U5.2(IN_1-2) ; port UART1_DBGR.CTRL
UART1_CTS: R56.1 U5.12(COM4) ; port UART1_DBGR.CTS
UART1_HWFC: R16.2 U5.10(IN_3-4) ; port UART1_DBGR.HWFC
UART1_RTS: U5.8(COM3) ; port UART1_DBGR.RTS
UART1_RxD: U5.4(COM2) ; port UART1_DBGR.RXD
UART1_TxD: U5.16(COM1) ; port UART1_DBGR.TXD
NetQ1_3: Q1.3(D2) R8.1 U7.5(OE) U8.5(OE)
NetR4_2: U6.16(COM1) ; port SWD3.SWDIO
NetR9_2: U6.4(COM2) ; port SWD3.SWDCLK
NetR37_2: U6.12(COM4) ; port SWD3.SWO
NetR38_2: U6.8(COM3) ; port SWD3.RESET
NetSB24_1: SB24.1 U6.11(NO4)

Not connected (* = marked no-connect by the designer): U4 1(NC1) 5(NC2) 9(NC3) 13(NC4); U5 1(NC1) 5(NC2) 9(NC3) 13(NC4); U6 1(NC1) 5(NC2) 9(NC3) 13(NC4)

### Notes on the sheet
- Level Shifters and switches
- Datasheet link (FSA2466UMX) <https://www.onsemi.com/pdf/datasheet/fsa2466-d.pdf>
- FSA2466UMX:
  NC/NO terminal: 6pF, OFF
  21pF, ON
- Flow control and Interface control signal controlled by IMCU

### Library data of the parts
C14-C16 C53 = C0201-100n: as C4 on sheet pca10156_sheet2_nRF54L15
Q1 = NX138AKS: as Q1 on sheet pca10156_sheet3_debugger
R8 R13-R17 R55 R56 = R0201-100k: as R6 on sheet pca10156_sheet3_debugger
R18 = R0201-1M0: Resistor, ±1%, 0.05W; Manufacturer: N.A.; Part number IPS: 00000001418; Part number Norautron: 26107108; Part number NEMS: 100100093; Component Status: Active; Pad Count: 2; Note: Chip Res 1%
SB24 = Solderbridge Shorted 0.4mm: as SB3 on sheet pca10156_sheet2_nRF54L15
U4-U6 = FSA2466UMX: Data / Audio Low-Voltage Dual DPDT Analog Switch; Manufacturer: ON Semiconductor; Part number IPS: 00000009986; Part number Norautron: 26500608; Part number NEMS: 101900422; Note: N.A.; Artikkelnr Noca: 15070069; Pad Count: 16; Component Status: Active
U7 U8 = TXB0302DQMR: 2-bit bidirectional voltage-level translator with automatic direction sensing; Manufacturer: Texas Instruments; Part number NEMS: 101900198; Component Status: Active; Pad Count: 8; Note: Fully Symmetric Supply Voltages; Artikkelnr Noca: N.A.

## Sheet pca10156_sheet5_misc.SchDoc: =BoardTitle+' - Misc'
size A3; Organization: Nordic Semiconductor; DocumentNumber: 5; Revision: 0.9.3; SheetNumber: 5; SheetTotal: 7; Author: STL1; CompanyName: Nordic Semiconductor; DrawnBy: STL1; DocumentSize: A4
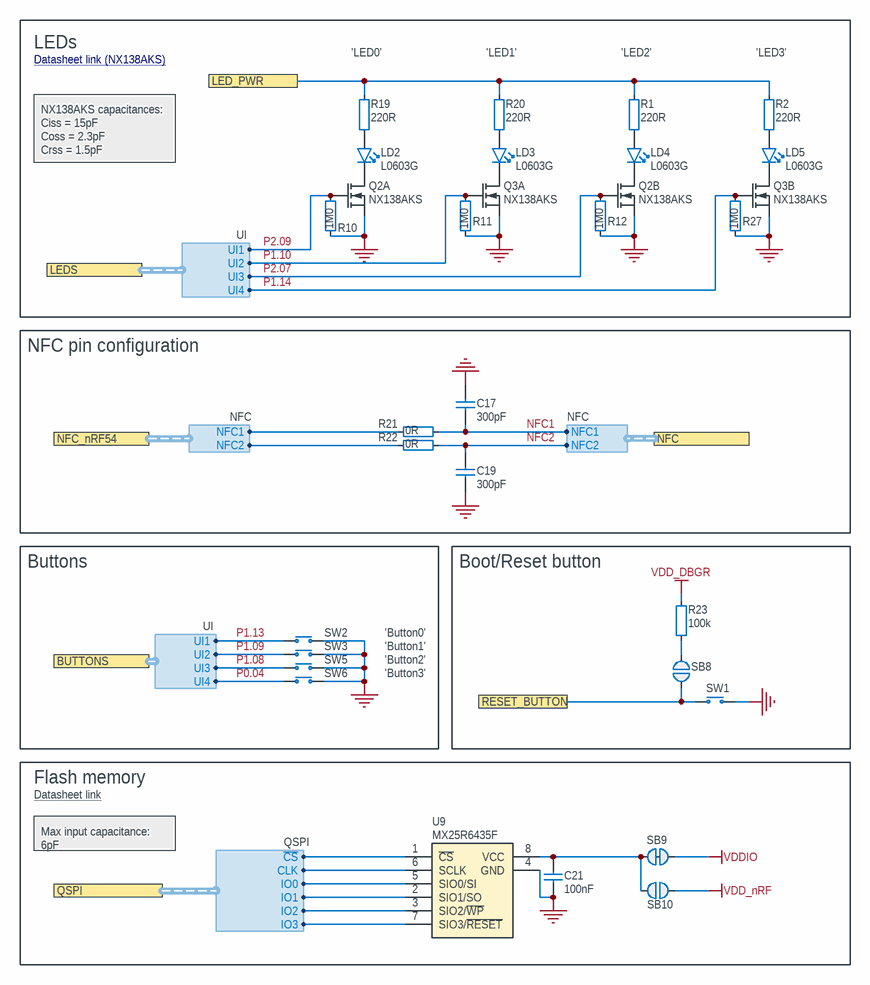
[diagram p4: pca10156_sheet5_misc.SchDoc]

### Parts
C17  300pF  [CAPC1005X04L]
C19  300pF  [CAPC1005X04L]
C21  100nF  [CAPC0603X03L_C]
LD2  L0603G  [LED_0603_G]
LD3  L0603G  [LED_0603_G]
LD4  L0603G  [LED_0603_G]
LD5  L0603G  [LED_0603_G]
Q2  NX138AKS  [TSSOP6]  (parts A,B of 2)
Q3  NX138AKS  [TSSOP6]  (parts A,B of 2)
R1  220R  [RESC0603X03L_C]
R2  220R  [RESC0603X03L_C]
R10  1M0  [RESC0603X03L_C]
R11  1M0  [RESC0603X03L_C]
R12  1M0  [RESC0603X03L_C]
R19  220R  [RESC0603X03L_C]
R20  220R  [RESC0603X03L_C]
R21  0R  [RESC1005X04L]
R22  0R  [RESC1005X04L]
R23  100k  [RESC0603X03L_C]
R27  1M0  [RESC0603X03L_C]
SB8  Solderbridge  [Solderbridge]  (value not drawn)  (no BOM)
SB9  Solderbridge  [Solderbridge_Shorted]  (value not drawn)  (net tie, no BOM)
SB10  Solderbridge  [Solderbridge]  (value not drawn)  (no BOM)
SW1  PB SW  [Switch-PB-6.2x6.3mm-SMD]  (value not drawn)
SW2  PB SW  [Switch-PB-6.2x6.3mm-SMD]  (value not drawn)
SW3  PB SW  [Switch-PB-6.2x6.3mm-SMD]  (value not drawn)
SW5  PB SW  [Switch-PB-6.2x6.3mm-SMD]  (value not drawn)
SW6  PB SW  [Switch-PB-6.2x6.3mm-SMD]  (value not drawn)
U9  MX25R6435F  [SON127P600X80_HS-9N]

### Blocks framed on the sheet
LEDs: LD2-LD5 Q2 Q3 R1 R2 R10-R12 R19 R20 R27
NFC pin configuration: C17 C19 R21 R22
Buttons: SW2 SW3 SW5 SW6
Boot/Reset button: R23 SB8 SW1
Flash memory: C21 SB9 SB10 U9

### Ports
BUTTONS (harness UI), LED_PWR, LEDS (harness UI), NFC (harness NFC), NFC_nRF54 (harness NFC), QSPI (harness QSPI), RESET_BUTTON

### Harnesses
NFC: NFC2, NFC1
UI: UI2, UI1, UI3, UI4
QSPI: ~{CS}, IO0, CLK, IO1, IO2, IO3
UI: UI2, UI3, UI4, UI1

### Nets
GND: C17.2 C19.1 C21.2 Q2.1(S1) Q2.4(S2) Q3.1(S1) Q3.4(S2) R10.2 R11.2 R12.2 R27.2 SW1.1(N.O) SW2.1(N.O) SW3.1(N.O) SW5.1(N.O) SW6.1(N.O) U9.4(GND) U9.9(GND)
VDD_DBGR: R23.2
VDD_nRF: SB10.1
VDDIO: SB9.1
NFC1: C17.1 R21.2 ; port NFC.NFC1
NFC2: C19.2 R22.2 ; port NFC.NFC2
P0.04: SW6.2(COM) ; port BUTTONS.UI4
P1.02/NFC1: R21.1 ; port NFC_nRF54.NFC1
P1.03/NFC2: R22.1 ; port NFC_nRF54.NFC2
P1.08: SW5.2(COM) ; port BUTTONS.UI3
P1.09: SW3.2(COM) ; port BUTTONS.UI2
P1.10: Q3.2(G1) R11.1 ; port LEDS.UI2
P1.13: SW2.2(COM) ; port BUTTONS.UI1
P1.14: Q3.5(G2) R27.1 ; port LEDS.UI4
P2.07: Q2.5(G2) R12.1 ; port LEDS.UI3
P2.09: Q2.2(G1) R10.1 ; port LEDS.UI1
NetC21_1: C21.1 SB9.2 SB10.2 U9.8(VCC)
NetLD2_1: LD2.1(C) Q2.6(D1)
NetLD2_2: LD2.2(A) R19.1
NetLD3_1: LD3.1(C) Q3.6(D1)
NetLD3_2: LD3.2(A) R20.1
NetLD4_1: LD4.1(C) Q2.3(D2)
NetLD4_2: LD4.2(A) R1.1
NetLD5_1: LD5.1(C) Q3.3(D2)
NetLD5_2: LD5.2(A) R2.1
NetR1_2: R1.2 R2.2 R19.2 R20.2 ; port LED_PWR
NetR23_1: R23.1 SB8.2
NetSB1_2: SB8.1 SW1.2(COM) ; port RESET_BUTTON
NetSB11_2: U9.1(~{CS}) ; port QSPI.~{CS}
NetSB12_2: U9.6(SCLK) ; port QSPI.CLK
NetSB13_2: U9.5(SIO0/SI) ; port QSPI.IO0
NetSB14_2: U9.2(SIO1/SO) ; port QSPI.IO1
NetSB15_2: U9.3(SIO2/~{WP}) ; port QSPI.IO2
NetSB16_2: U9.7(SIO3/~{RESET}) ; port QSPI.IO3

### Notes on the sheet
- Datasheet link (NX138AKS) <https://assets.nexperia.com/documents/data-sheet/NX138AKS.pdf>
- (near R19) 'LED0'
- (near R20) 'LED1'
- (near R1) 'LED2'
- (near R2) 'LED3'
- NX138AKS capacitances:
  Ciss = 15pF
  Coss = 2.3pF
  Crss = 1.5pF
- 'Button1'
- 'Button2'
- 'Button3'
- 'Button0'
- Datasheet link <https://www.mxic.com.tw/Lists/Datasheet/Attachments/8868/MX25R6435F,%20Wide%20Range,%2064Mb,%20v1.6.pdf>
- Max input capacitance: 6pF

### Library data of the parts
C17 C19 = C0402-300p: Capacitor, C0G, ±5%, 50V; Manufacturer: N.A.; Part number IPS: 00000007788; Part number NEMS: 100200155; Artikkelnr Noca: 20020004; Pad Count: 2; Component Status: Active
C21 = C0201-100n: as C4 on sheet pca10156_sheet2_nRF54L15
LD2-LD5 = VS 25C7M5: as LD1 on sheet pca10156_sheet3_debugger
Q2 Q3 = NX138AKS: as Q1 on sheet pca10156_sheet3_debugger
R1 R2 R19 R20 = R0201-220: Resistor, ±1%, 0.05W; Manufacturer: N.A.; Part number IPS: 00000000863; Part number Norautron: 26107014; Part number NEMS: 100100032; Note: Chip Res 1%; Pad Count: 2; Component Status: Active
R10-R12 R27 = R0201-1M0: as R18 on sheet pca10156_sheet4_level_shifters
R21 R22 = R0402-0R: Resistor, ±5%, 0.063W; Manufacturer: N.A.; Part number IPS: 00000007128; Part number NEMS: 100100109; Component Status: Active; Pad Count: 2; Note: Chip Res 5%; Artikkelnr Noca: 27049000
R23 = R0201-100k: as R6 on sheet pca10156_sheet3_debugger
SB8 SB10 = Solderbridge: as SB1 on sheet pca10156_sheet1_connections
SB9 = Solderbridge Shorted: as SB2 on sheet pca10156_sheet1_connections
SW1-SW3 SW5 SW6 = Switch-PB-6.2x6.3mm-SMD: Tactile Switch, SPNO, SMD, 160gf, 6.2x6.3x2.5mm; Manufacturer: Dailywell; Manufacturer Part Number: TS604VM1-025BR-R; Part number IPS: 00000007812; Part number NEMS: 101500001, 101500133; Note: N.A.; Artikkelnr Noca: 50019106; Pad Count: 4; Component Status: Active
U9 = MX25R6435FZNIL0: Ultra low power, 64M-bit, serial multi I/O flash memory; Manufacturer: Macronix; Part number IPS: 00000004370; Part number NEMS: 101900438; Note: N.A.; Artikkelnr Noca: 15020015; Pad Count: 8; Component Status: Active

## Sheet pca10156_sheet6_power_supply.SchDoc: =BoardTitle+' - Power Supply'
size A3; Organization: Nordic Semiconductor; DocumentNumber: 6; Revision: 0.9.3; SheetNumber: 6; SheetTotal: 7; Author: STL1; CompanyName: Nordic Semiconductor; DrawnBy: STL1; DocumentSize: A4
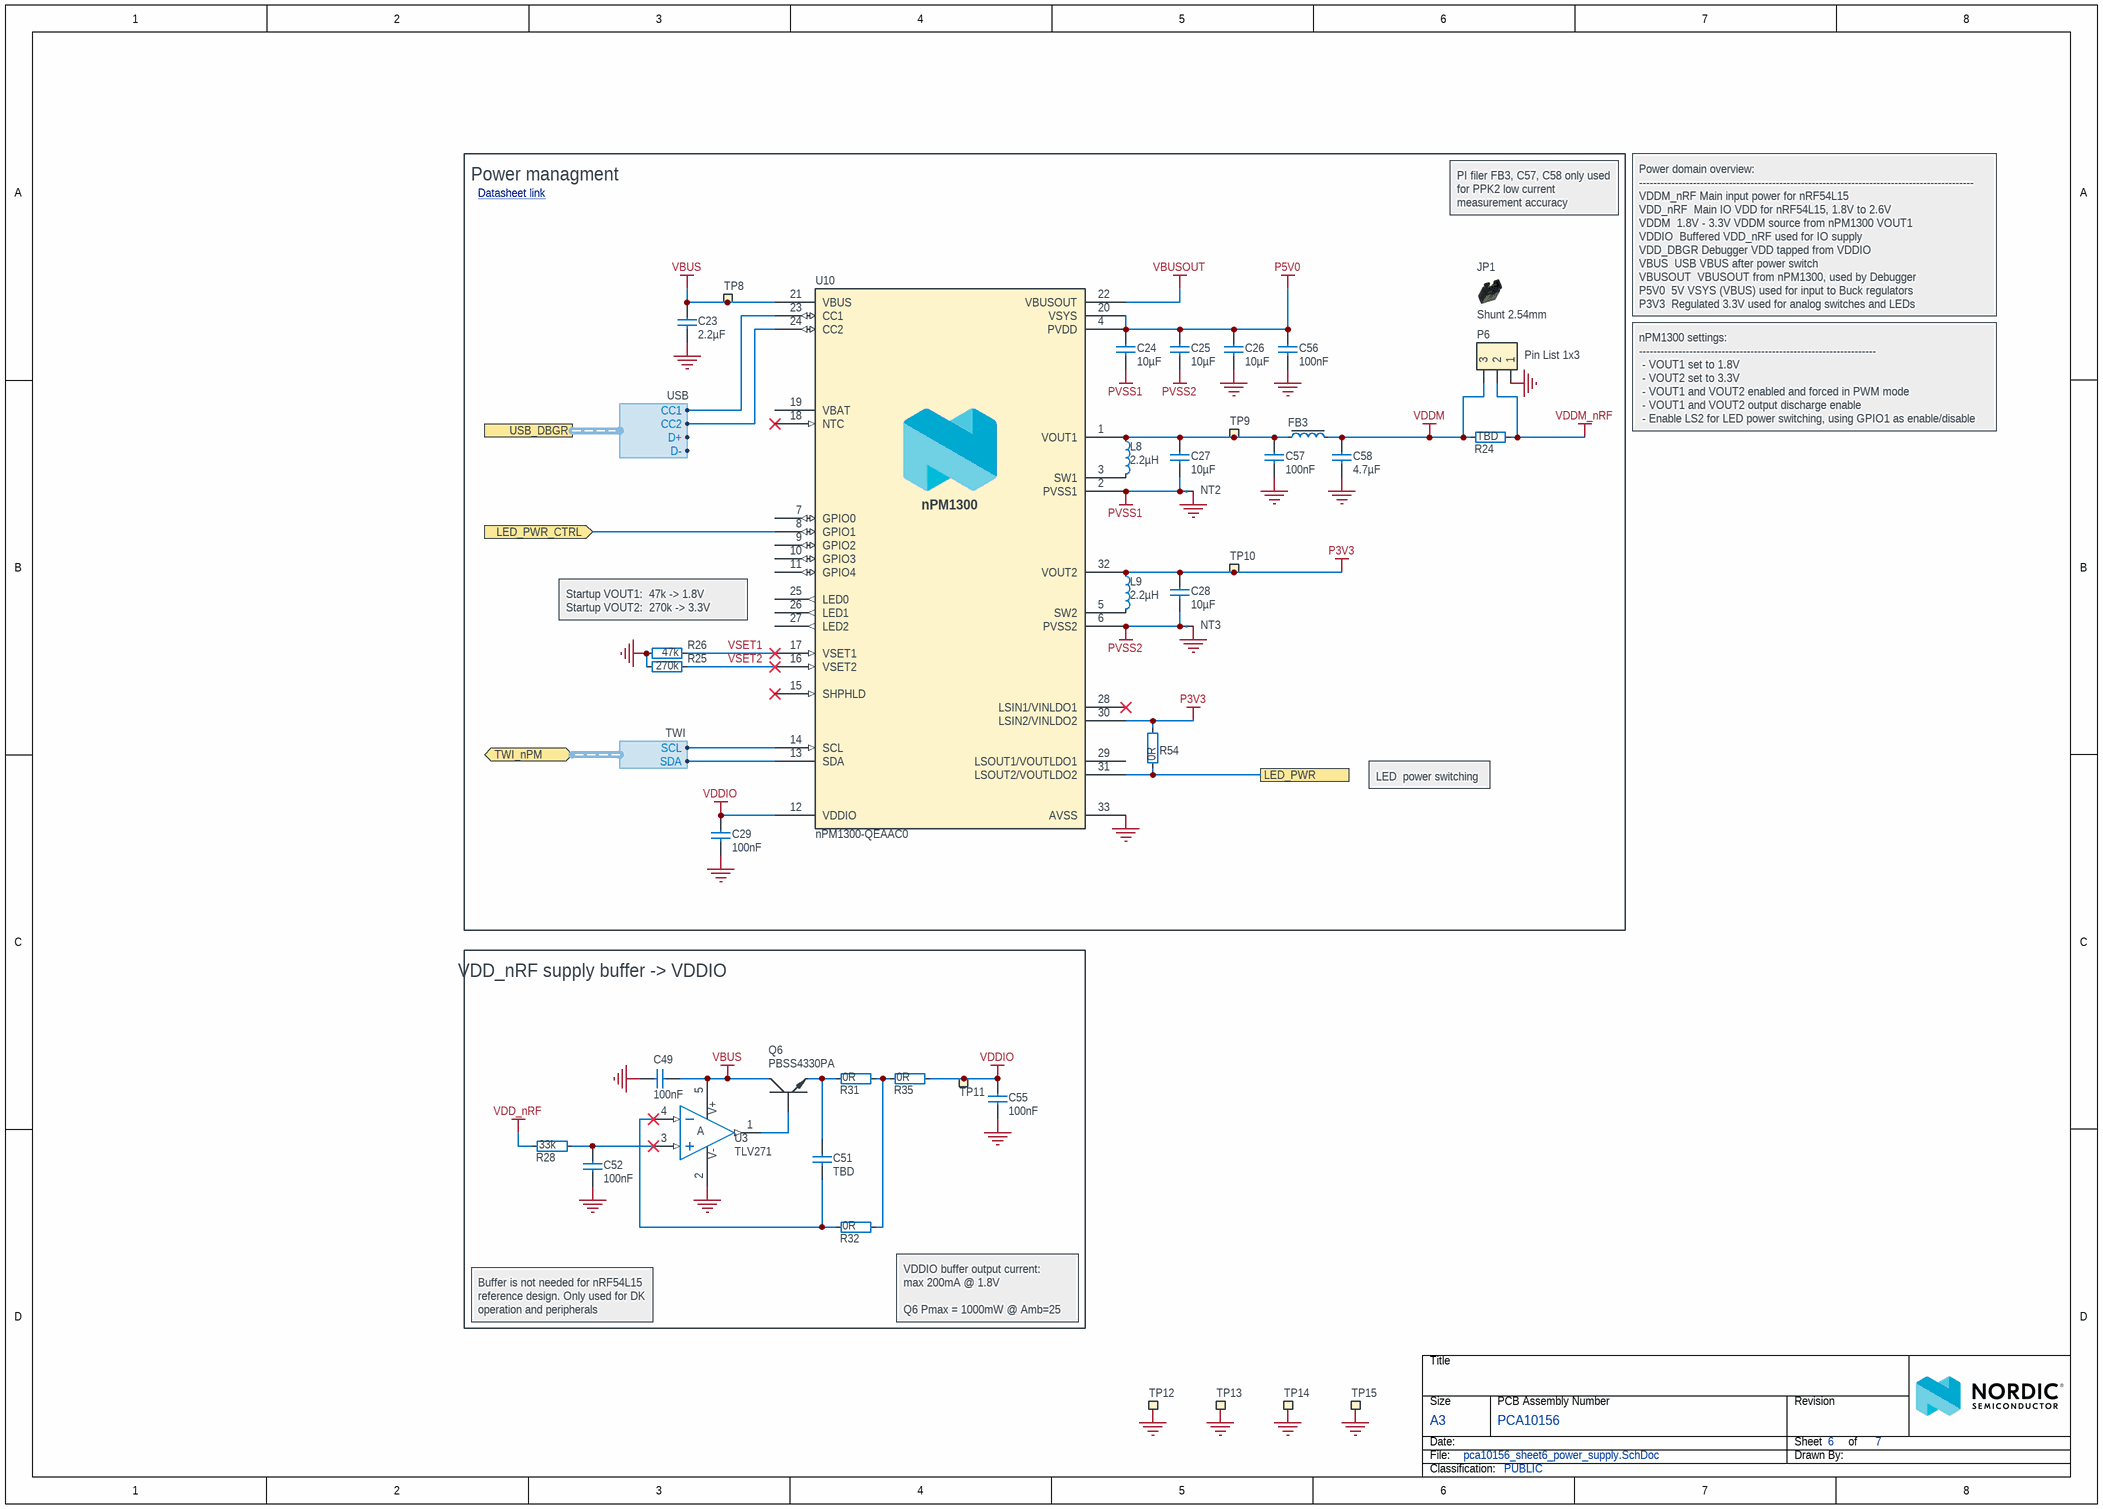
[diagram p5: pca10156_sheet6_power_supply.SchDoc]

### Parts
C23  2.2µF  [CAPC1005X04L]
C24  10µF  [CAPC1608X06L]
C25  10µF  [CAPC1608X06L]
C26  10µF  [CAPC1608X06L]
C27  10µF  [CAPC1608X06L]
C28  10µF  [CAPC1608X06L]
C29  100nF  [CAPC0603X03L_C]
C49  100nF  [CAPC0603X03L_C]
C51  TBD  [CAPC0603X03L_C]
C52  100nF  [CAPC0603X03L_C]
C55  100nF  [CAPC0603X03L_C]
C56  100nF  [CAPC0603X03L_C]
C57  100nF  [CAPC0603X03L_C]
C58  4.7µF  [CAPC1608X06L]
FB3  120R/0.55A  [INDC1005X04L]  (value not drawn)
JP1  Shunt 2.54mm  [Shunt_2.54mm_Vertical]
L8  2.2µH  [INDC2016X10N]
L9  2.2µH  [INDC2016X10N]
NT2  Net tie  [2 PIN STARPOINT]  (value not drawn)  (net tie, no BOM)
NT3  Net tie  [2 PIN STARPOINT]  (value not drawn)  (net tie, no BOM)
P6  Pin List 1x3  [LIST_1x3_SMD]
Q6  PBSS4330PA  [DFN105P200X65-3N_v2]
R24  TBD  [RESC1005X04L]
R25  270k  [RESC0603X03L_C]
R26  47k  [RESC0603X03L_C]
R28  33k  [RESC0603X03L_C]
R31  0R  [RESC0603X03L_C]
R32  0R  [RESC0603X03L_C]
R35  0R  [RESC0603X03L_C]
R54  0R  [RESC0603X03L_C]
TP8  Ø1.5mm,SMD  [TP_SMD_D1.5mm]  (value not drawn)  (no BOM)
TP9  Ø1.5mm,SMD  [TP_SMD_D1.5mm]  (value not drawn)  (no BOM)
TP10  Ø1.5mm,SMD  [TP_SMD_D1.5mm]  (value not drawn)  (no BOM)
TP11  Ø1.5mm,SMD  [TP_SMD_D1.5mm]  (value not drawn)  (no BOM)
TP12  Ø1.5mm,SMD  [TP_SMD_D1.5mm]  (value not drawn)  (no BOM)
TP13  Ø1.5mm,SMD  [TP_SMD_D1.5mm]  (value not drawn)  (no BOM)
TP14  Ø1.5mm,SMD  [TP_SMD_D1.5mm]  (value not drawn)  (no BOM)
TP15  Ø1.5mm,SMD  [TP_SMD_D1.5mm]  (value not drawn)  (no BOM)
U3  TLV271  [SOT95P280X145-5N]
U10  nPM1300-QEAAC0  [Nordic_QFN50P500X500X90-33N]

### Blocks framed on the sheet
Power managment: C23-C29 C56-C58 FB3 JP1 L8 L9 NT2 NT3 P6 R24-R26 R54 TP8-TP10 U10
VDD_nRF supply buffer -> VDDIO: C49 C51 C52 C55 Q6 R28 R31 R32 R35 TP11 U3

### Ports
LED_PWR, LED_PWR_CTRL (in), TWI_nPM (bidir, harness TWI), USB_DBGR (harness USB)

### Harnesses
TWI: SDA, SCL
USB: D+, D-, CC1, CC2

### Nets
GND: C23.1 C26.1 C29.2 C49.2 C52.2 C55.2 C56.1 C57.1 C58.2 NT2.1 NT3.1 P6.1 R25.2 R26.2 TP12.1 TP13.1 TP14.1 TP15.1 U3.2(VSS) U10.33(AVSS)
P3V3: C28.2 L9.1 R54.2 TP10.1 U10.30(LSIN2/VINLDO2) U10.32(VOUT2)
P5V0: C24.2 C25.2 C26.2 C56.2 U10.4(PVDD) U10.20(VSYS)
PVSS1: C24.1 C27.1 NT2.2 U10.2(PVSS1)
PVSS2: C25.1 C28.1 NT3.2 U10.6(PVSS2)
VBUS: C23.2 C49.1 Q6.3(C) TP8.1 U3.5(VDD) U10.21(VBUS)
VBUSOUT: U10.22(VBUSOUT)
VDD_nRF: R28.1
VDDIO: C29.1 C55.1 R35.2 TP11.1 U10.12(VDDIO)
VDDM: C58.1 FB3.2 P6.3 R24.2
VDDM_nRF: P6.2 R24.1
LED_PWR_CTRL: U10.8(GPIO1) ; port LED_PWR_CTRL
TWI0_SCL: U10.14(SCL) ; port TWI_nPM.SCL
TWI0_SDA: U10.13(SDA) ; port TWI_nPM.SDA
VSET1: R26.1 U10.17(VSET1)
VSET2: R25.1 U10.16(VSET2)
NetC27_2: C27.2 C57.2 FB3.1 L8.1 TP9.1 U10.1(VOUT1)
NetC51_1: C51.1 R32.1 U3.4(IN-)
NetC51_2: C51.2 Q6.2(E) R31.1
NetC52_1: C52.1 R28.2 U3.3(IN+)
NetJ3_A5: U10.23(CC1) ; port USB_DBGR.CC1
NetJ3_B5: U10.24(CC2) ; port USB_DBGR.CC2
NetL8_2: L8.2 U10.3(SW1)
NetL9_2: L9.2 U10.5(SW2)
NetQ6_1: Q6.1(B) U3.1(OUT)
NetR1_2: R54.1 U10.31(LSOUT2/VOUTLDO2) ; port LED_PWR
NetR31_2: R31.2 R32.2 R35.1

Not connected (* = marked no-connect by the designer): U10 7(GPIO0) 9(GPIO2) 10(GPIO3) 11(GPIO4) 15(SHPHLD)* 18(NTC)* 19(VBAT) 25(LED0) 26(LED1) 27(LED2) 28(LSIN1/VINLDO1)* 29(LSOUT1/VOUTLDO1)

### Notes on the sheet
- Datasheet link <https://infocenter.nordicsemi.com/index.jsp?topic=%2Fstruct_pmic%2Fstruct%2Fnpm1300.html>
- PI filer FB3, C57, C58 only used for PPK2 low current measurement accuracy
- Power domain overview:
  ---------------------------------------------------------------------------------------------
  VDDM_nRF	Main input power for nRF54L15
  VDD_nRF		Main IO VDD for nRF54L15, 1.8V to 2.6V
  VDDM		1.8V - 3.3V VDDM source from nPM1300 VOUT1
  VDDIO		Buffered VDD_nRF used for IO supply
  VDD_DBGR	Debugger VDD tapped from VDDIO
  VBUS		USB VBUS after power switch
  VBUSOUT		VBUSOUT from nPM1300, used by Debugger
  P5V0		5V VSYS (VBUS) used for input to Buck regulators
  P3V3		Regulated 3.3V used for analog switches and LEDs
- nPM1300 settings:
  ------------------------------------------------------------------
  - VOUT1 set to 1.8V
  - VOUT2 set to 3.3V
  - VOUT1 and VOUT2 enabled and forced in PWM mode
  - VOUT1 and VOUT2 output discharge enable
  - Enable LS2 for LED power switching, using GPIO1 as enable/disable signal.
- Startup VOUT1:  47k -> 1.8V
  Startup VOUT2:  270k -> 3.3V
- LED  power switching
- Buffer is not needed for nRF54L15 reference design. Only used for DK operation and peripherals
- (near R32) VDDIO buffer output current:
  max 200mA @ 1.8V
  Q6 Pmax = 1000mW @ Amb=25

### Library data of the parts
C23 = C0402-2µ2-10V: Capacitor, X5R, ±10%; Manufacturer: N.A.; Part number NEMS: 100200376; Component Status: Active; Pad Count: 2; Note: 10V
C24-C28 = C0603-10µ-10V-X7T-GRM188D71A106MA73: Capacitor, X7T, ±20%, 10V; Manufacturer: Murata; Part number IPS: 00000004696; Part number NEMS: 100200414; Component Status: Active; Pad Count: 2; Note: 10VDC; Artikkelnr Noca: N.A.
C29 C49 C52 C55 = C0201-100n: as C4 on sheet pca10156_sheet2_nRF54L15
C51 = C0201-TBD: Chip Cap 0201; Manufacturer: N.A.; Part number NEMS: 100200002; Component Status: Active; Pad Count: 2; Assembly: Not Mounted
C56 = C0201-100n: Capacitor, X5R, ±10%; Manufacturer: N.A.; Part number IPS: 00000001248, 00000002505; Part number Norautron: 262071862; Part number NEMS: 100200078; Note: 16V; Assembly: Not Mounted; Pad Count: 2; Component Status: Active
C57 = C0201-100n: Capacitor, X5R, ±10%; Manufacturer: N.A.; Part number IPS: 00000001248, 00000002505; Part number Norautron: 262071862; Part number NEMS: 100200078; Note: 16V; Pad Count: 2; Component Status: Active
C58 = C0603-4µ7-10V-X7S: as C42 on sheet pca10156_sheet3_debugger
FB3 = FB0402-120R@100M-500mA: Ferrite Bead, 120 Ohm @ 100MHz, 500mA, 250 mOhm Max; Manufacturer: Murata; Manufacturer Part Number: BLM15AG121SN1D; Part number IPS: 00000009954; Part number Norautron: 265230631; Part number NEMS: 100300099; Note: Chip EMIFIL Inductor Type Chip Ferrite Bead; Artikkelnr Noca: 33029317; Pad Count: 2; Component Status: Active
JP1 = SHUNT JUMPER 2.54mm Black Vertical: Shunt Jumper 2.54mm Black, open top; Manufacturer: WCON; Manufacturer Part Number: 3710-6001OS0B05; Part number NEMS: 100500728; Pad Count: 2; Note: N.A.; Component Status: Active; System: Connector
L8 L9 = L0806-2µ2-2500mA-73mOhm-CIGT201610EH2R2MNE: Inductor, Irms=2.5A, Isat=2.9A, ±20%, DCR=73mΩ; Manufacturer: Samsung Electro-Mechanics America; Part number Norautron: 26521789; Part number NEMS: 100300400; Component Status: Active; Pad Count: 2; Note: Unshielded Thin Film Inductor; Artikkelnr Noca: N.A.
NT2 NT3 = 2 pin starpoint: Starpoint; Manufacturer: N.A.; Part number NEMS: 100500603; Pad Count: 2; Component Status: Active; System: Connector
P6 = Pin List 1x3 SMD: Pin List 1x3, 2.54mm (100mil), SMD; Manufacturer: WCON; Manufacturer Part Number: 1125-1103S0M116CR04; Part number Norautron: 26470016; Part number NEMS: 100500306; Note: N.A.; Pad Count: 3; Component Status: Active; System: Connector
Q6 = PBSS4330PA,115: 30V, 3A, 2.1W, G=270, NPN Transistor; Manufacturer: Nexperia; Part number NEMS: 101300184; Component Status: Active; Pad Count: 3; Note: N.A.
R24 = R0402-TBD: Chip Res 0402; Manufacturer: N.A.; Part number NEMS: 100100282; Component Status: Active; Pad Count: 2; Assembly: Not Mounted
R25 = R0201-270k: Resistor, ±1%, 0.05W; Manufacturer: N.A.; Part number IPS: 00000004317; Part number NEMS: 100100086; Component Status: Active; Pad Count: 2; Note: Chip Res 1%
R26 = R0201-47k: Resistor, ±1%, 0.05W; Manufacturer: N.A.; Part number IPS: 00000001423; Part number NEMS: 100100076; Component Status: Active; Pad Count: 2; Note: Chip Res 1%
R28 = R0201-33k: Resistor, ±1%, 0.05W; Manufacturer: N.A.; Part number IPS: 00000001708; Part number NEMS: 100100073; Component Status: Active; Pad Count: 2; Note: Chip Res 1%
R31 R32 R35 = R0201-0R: as R3 on sheet pca10156_sheet2_nRF54L15
R54 = R0201-0R: Resistor, ±5%, 0.05W; Manufacturer: N.A.; Part number IPS: 00000003245; Part number NEMS: 100100001; Component Status: Active; Pad Count: 2; Note: Chip Res 5%; Assembly: Not Mounted
TP8-TP15 = TP_SMD_Ø1.5MM: as TP1 on sheet pca10156_sheet2_nRF54L15
U3 = TLV271CW5-7: Dual rail to rail CMOS Amplifier; Manufacturer: Diodes Incorporated; Part number NEMS: 101900398; Component Status: Active; Pad Count: 5; Note: N.A.
U10 = nPM1300-QEAAC0: Li-Ion/Li-Polymer USB-C battery charger with high efficiency buck regulators, LDOs or load switches, LED drivers, TWI and VBUSOUT; Manufacturer: Nordic Semiconductor; Part number NEMS: 102000306; Component Status: Active; Pad Count: 33; Note: Production version; Artikkelnr Noca: N.A.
